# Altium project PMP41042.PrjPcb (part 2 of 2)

## Sheet PMP41042_sheet2.SchDoc
size A2; SheetNumber: 2; SheetTotal: 3
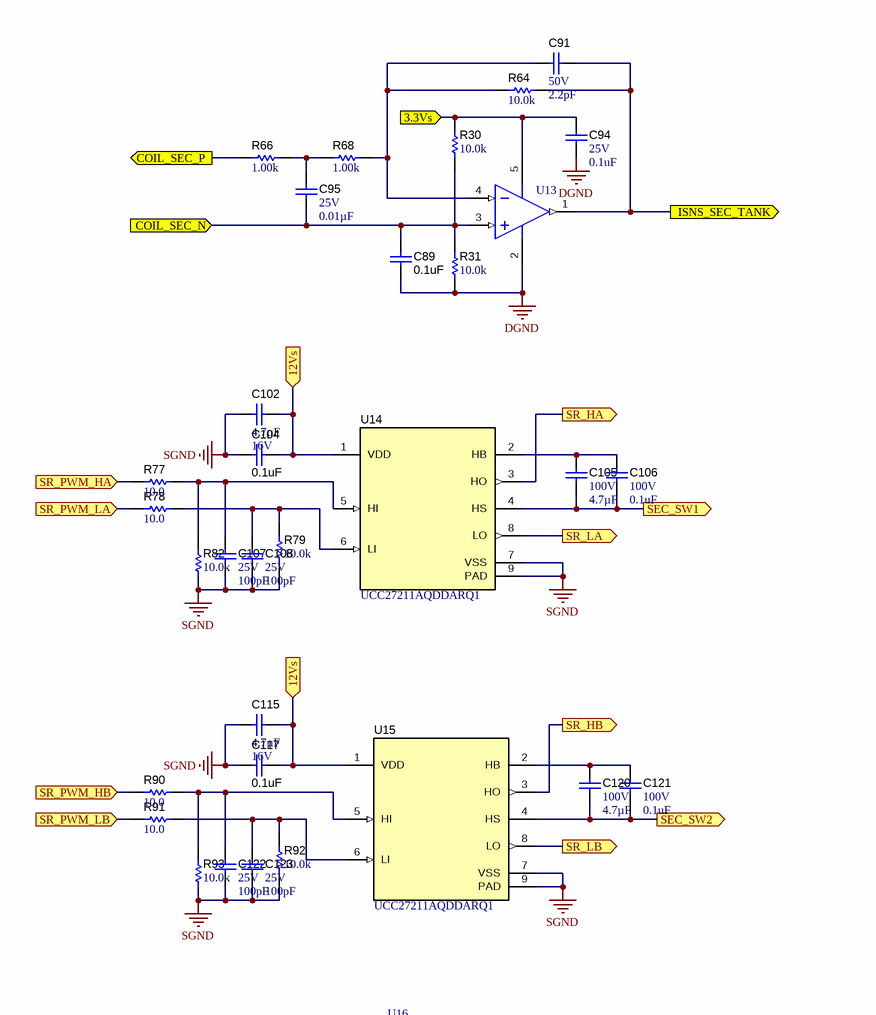
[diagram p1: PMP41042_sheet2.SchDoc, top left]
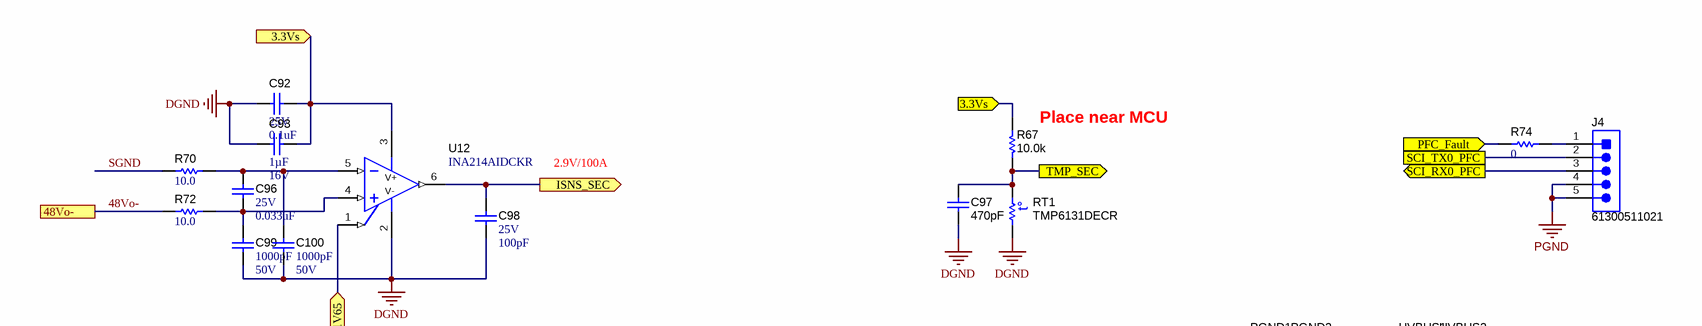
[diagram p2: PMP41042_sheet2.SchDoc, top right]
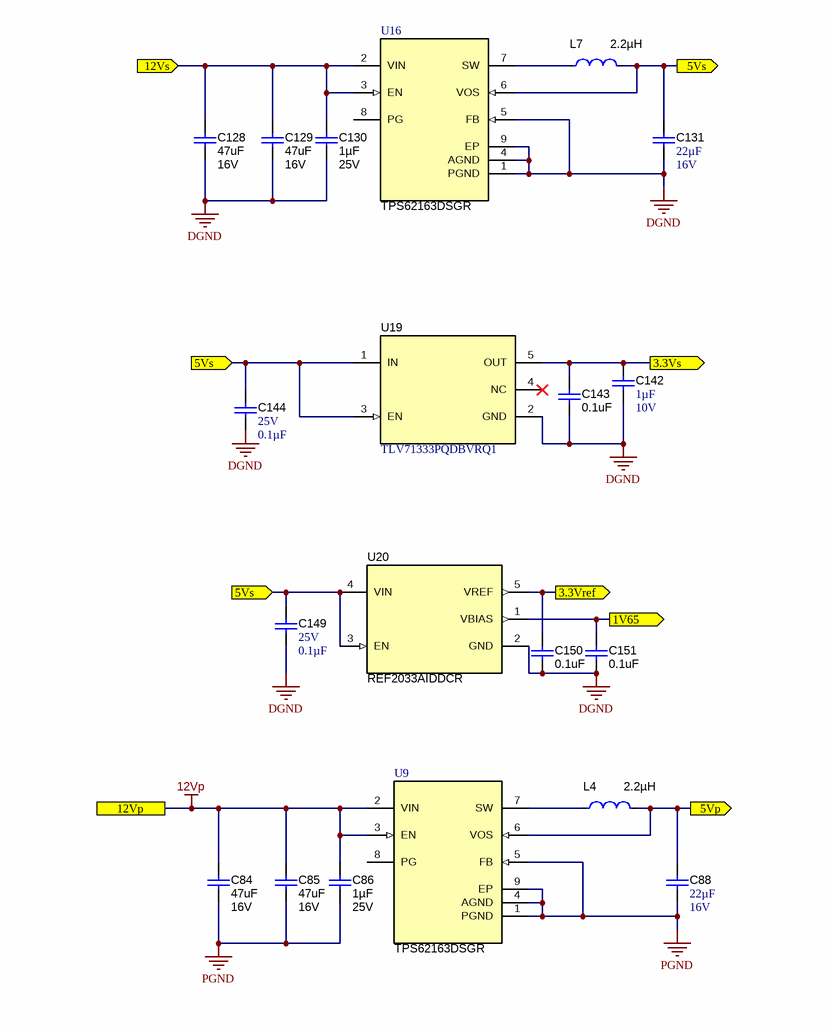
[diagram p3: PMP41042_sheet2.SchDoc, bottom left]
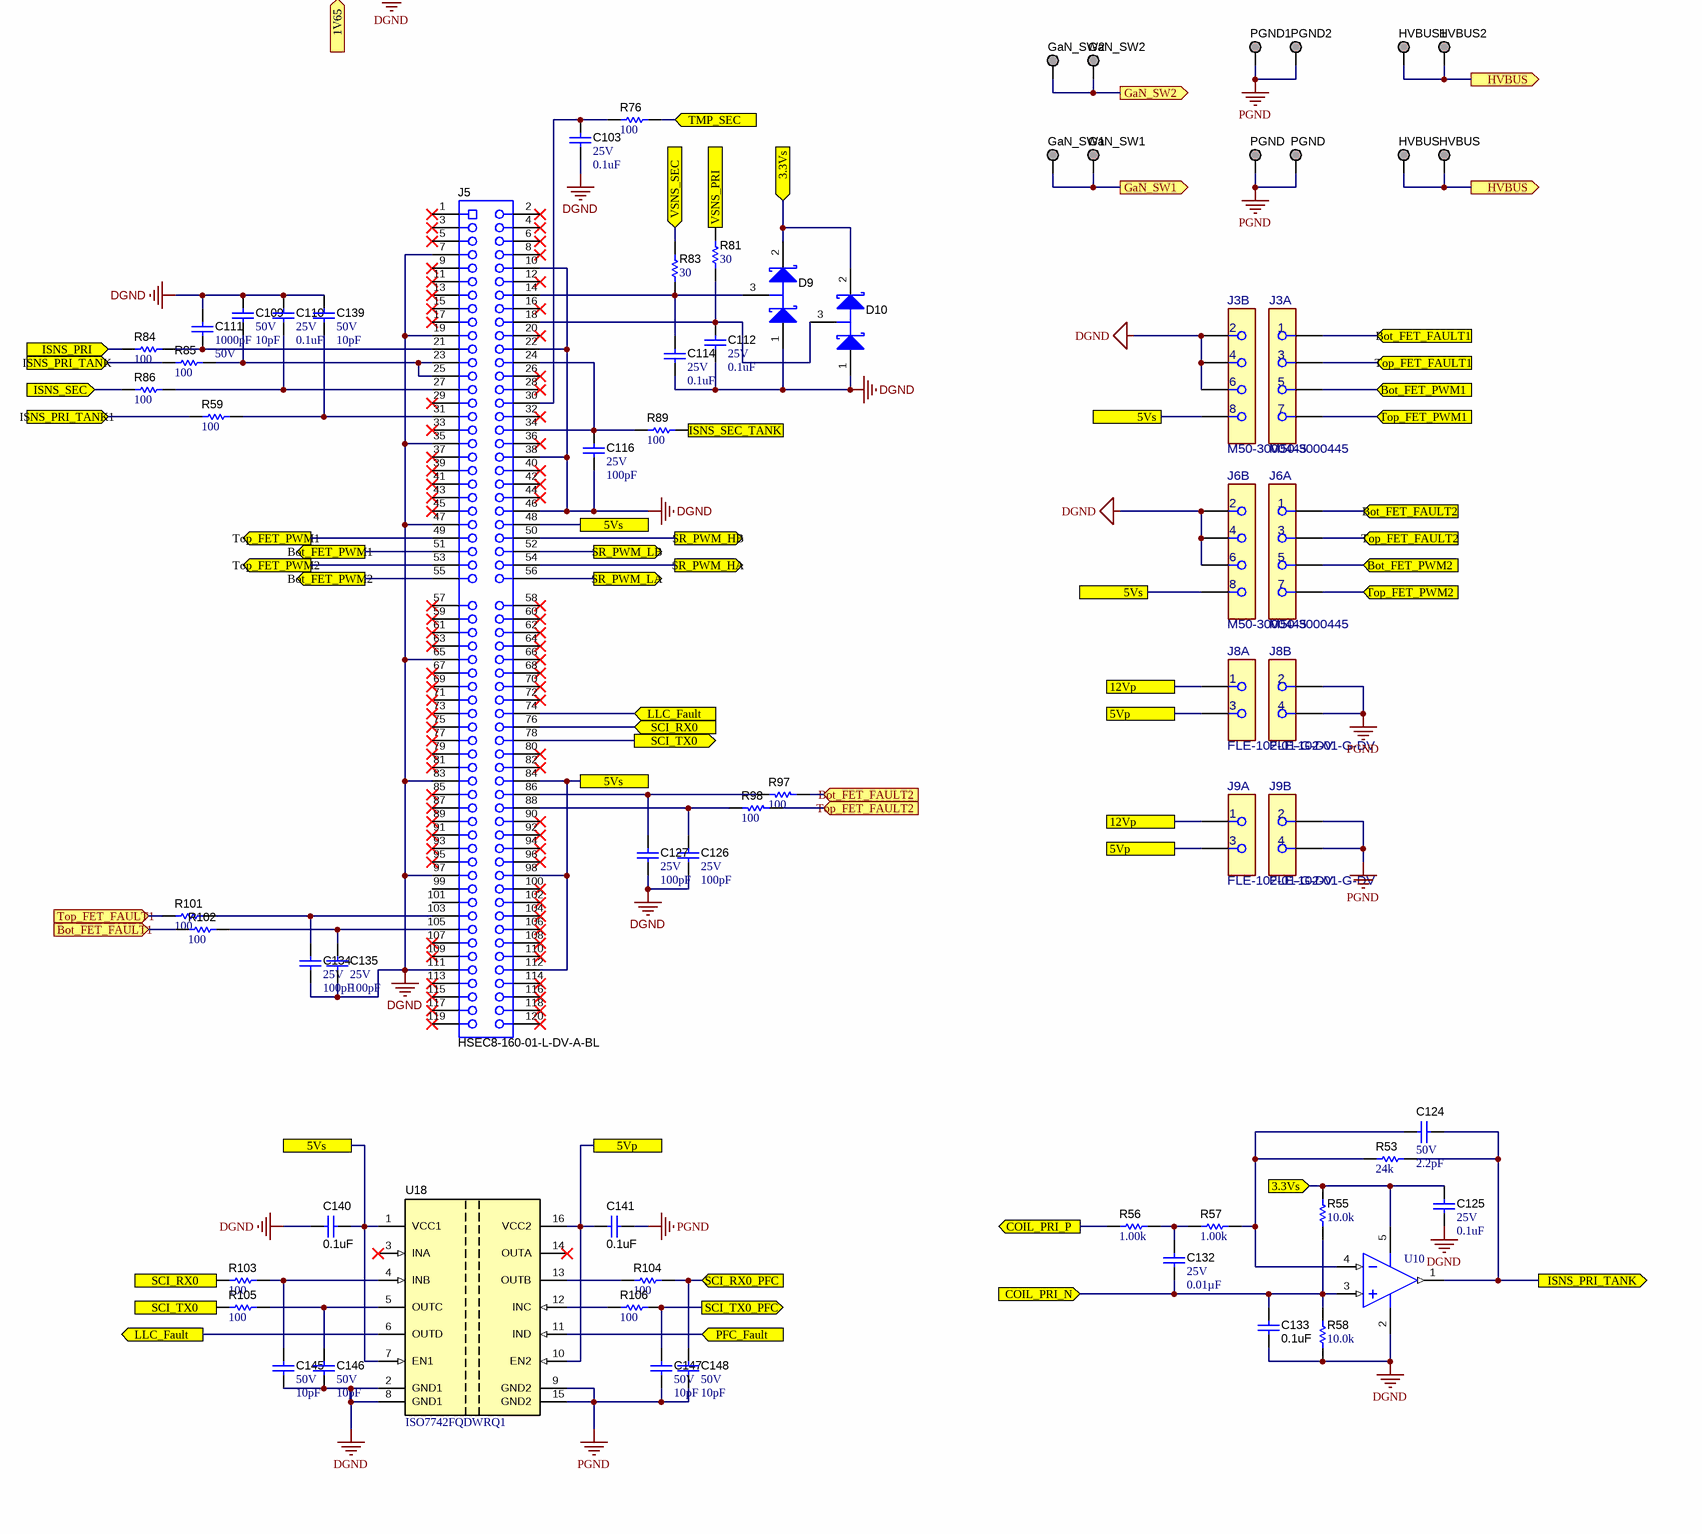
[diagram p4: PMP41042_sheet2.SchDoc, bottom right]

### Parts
(Parts that share a designator on the sheet are numbered #1, #2 ... from top to bottom, then left to right.)
C84  ValueDisplayed: 47uF  Value2: 16V  [1210_270]  (hidden comment: GRM32ER61C476KE15L)
C85  ValueDisplayed: 47uF  Value2: 16V  [1210_270]  (hidden comment: GRM32ER61C476KE15L)
C86  Cap_F: 1µF  VDC_V: 25V  [0805_HV]  (hidden comment: C0805C105K3RACTU)
C88  ValueDisplayed: 22µF  VDC_V: 16V  [0805_HV]  (hidden comment: CL21A226KOQNNNE)
C89  ValueDisplayed: 0.1uF  [0402]  (hidden comment: 0402YC104KAT2A)
C91  VDC_V: 50V  ValueDisplayed: 2.2pF  [0402]  (hidden comment: GRM1555C1H2R2CA01D)
C92  VDC_V: 25V  ValueDisplayed: 0.1uF  [0402]  (hidden comment: GRM155R71E104KE14D)
C93  Cap_F: 1µF  VDC_V: 16V  [0603]  (hidden comment: CGA3E1X7R1C105K080AC)
C94  VDC_V: 25V  ValueDisplayed: 0.1uF  [0402]  (hidden comment: GRM155R71E104KE14D)
C95  VDC_V: 25V  ValueDisplayed: 0.01µF  [0402]  (hidden comment: CL05B103KA5NNNC)
C96  VDC_V: 25V  ValueDisplayed: 0.033uF  [0402]  (hidden comment: GRM155R71E333KA88D)
C97  ValueDisplayed: 470pF  [0402]  (hidden comment: CGA2B2X7R1H471K050BA)
C98  VDC_V: 25V  ValueDisplayed: 100pF  [0402]  (hidden comment: C0402C101J3GACTU)
C99  ValueDisplayed: 1000pF  VDC_V: 50V  [0402]  (hidden comment: CL05B102KB5NNNC)
C100  ValueDisplayed: 1000pF  VDC_V: 50V  [0402]  (hidden comment: CL05B102KB5NNNC)
C102  Cap_F: 4.7µF  VDC_V: 16V  [0603]  (hidden comment: GRM188Z71C475KE21D)
C103  VDC_V: 25V  ValueDisplayed: 0.1uF  [0402]  (hidden comment: GRM155R71E104KE14D)
C104  ValueDisplayed: 0.1uF  [0402]  (hidden comment: 0402YC104KAT2A)
C105  VDC_V: 100V  ValueDisplayed: 4.7µF  [1206_190]  (hidden comment: 12061Z475MAT2A)
C106  VDC_V: 100V  ValueDisplayed: 0.1uF  [0402]  (hidden comment: GRM155R62A104KE14D)
C107  VDC_V: 25V  ValueDisplayed: 100pF  [0402]  (hidden comment: C0402C101J3GACTU)
C108  VDC_V: 25V  ValueDisplayed: 100pF  [0402]  (hidden comment: C0402C101J3GACTU)
C109  VDC_V: 50V  ValueDisplayed: 10pF  [0402]  (hidden comment: GRM1555C1H100JA01D)
C110  VDC_V: 25V  ValueDisplayed: 0.1uF  [0402]  (hidden comment: GRM155R71E104KE14D)
C111  ValueDisplayed: 1000pF  VDC_V: 50V  [0402]  (hidden comment: CL05B102KB5NNNC)
C112  VDC_V: 25V  ValueDisplayed: 0.1uF  [0402]  (hidden comment: GRM155R71E104KE14D)
C114  VDC_V: 25V  ValueDisplayed: 0.1uF  [0402]  (hidden comment: GRM155R71E104KE14D)
C115  Cap_F: 4.7µF  VDC_V: 16V  [0603]  (hidden comment: GRM188Z71C475KE21D)
C116  VDC_V: 25V  ValueDisplayed: 100pF  [0402]  (hidden comment: C0402C101J3GACTU)
C117  ValueDisplayed: 0.1uF  [0402]  (hidden comment: 0402YC104KAT2A)
C120  VDC_V: 100V  ValueDisplayed: 4.7µF  [1206_190]  (hidden comment: 12061Z475MAT2A)
C121  VDC_V: 100V  ValueDisplayed: 0.1uF  [0402]  (hidden comment: GRM155R62A104KE14D)
C122  VDC_V: 25V  ValueDisplayed: 100pF  [0402]  (hidden comment: C0402C101J3GACTU)
C123  VDC_V: 25V  ValueDisplayed: 100pF  [0402]  (hidden comment: C0402C101J3GACTU)
C124  VDC_V: 50V  ValueDisplayed: 2.2pF  [0402]  (hidden comment: GRM1555C1H2R2CA01D)
C125  VDC_V: 25V  ValueDisplayed: 0.1uF  [0402]  (hidden comment: GRM155R71E104KE14D)
C126  VDC_V: 25V  ValueDisplayed: 100pF  [0402]  (hidden comment: C0402C101J3GACTU)
C127  VDC_V: 25V  ValueDisplayed: 100pF  [0402]  (hidden comment: C0402C101J3GACTU)
C128  ValueDisplayed: 47uF  Value2: 16V  [1210_270]  (hidden comment: GRM32ER61C476KE15L)
C129  ValueDisplayed: 47uF  Value2: 16V  [1210_270]  (hidden comment: GRM32ER61C476KE15L)
C130  Cap_F: 1µF  VDC_V: 25V  [0805_HV]  (hidden comment: C0805C105K3RACTU)
C131  ValueDisplayed: 22µF  VDC_V: 16V  [0805_HV]  (hidden comment: CL21A226KOQNNNE)
C132  VDC_V: 25V  ValueDisplayed: 0.01µF  [0402]  (hidden comment: CL05B103KA5NNNC)
C133  ValueDisplayed: 0.1uF  [0402]  (hidden comment: 0402YC104KAT2A)
C134  VDC_V: 25V  ValueDisplayed: 100pF  [0402]  (hidden comment: C0402C101J3GACTU)
C135  VDC_V: 25V  ValueDisplayed: 100pF  [0402]  (hidden comment: C0402C101J3GACTU)
C139  VDC_V: 50V  ValueDisplayed: 10pF  [0402]  (hidden comment: GRM1555C1H100JA01D)
C140  ValueDisplayed: 0.1uF  [0402]  (hidden comment: C1005X7R1H104K050BB)
C141  ValueDisplayed: 0.1uF  [0402]  (hidden comment: C1005X7R1H104K050BB)
C142  Cap_F: 1µF  VDC_V: 10V  [0603]  (hidden comment: GRM188R71A105KA61D)
C143  ValueDisplayed: 0.1uF  [0402]  (hidden comment: CC0402KRX7R5BB104)
C144  VDC_V: 25V  ValueDisplayed: 0.1µF  [0402]  (hidden comment: CGA2B3X7R1E104K050BB)
C145  VDC_V: 50V  ValueDisplayed: 10pF  [0402]  (hidden comment: GRM1555C1H100JA01D)
C146  VDC_V: 50V  ValueDisplayed: 10pF  [0402]  (hidden comment: GRM1555C1H100JA01D)
C147  VDC_V: 50V  ValueDisplayed: 10pF  [0402]  (hidden comment: GRM1555C1H100JA01D)
C148  VDC_V: 50V  ValueDisplayed: 10pF  [0402]  (hidden comment: GRM1555C1H100JA01D)
C149  VDC_V: 25V  ValueDisplayed: 0.1µF  [0402]  (hidden comment: CGA2B3X7R1E104K050BB)
C150  ValueDisplayed: 0.1uF  [0402]  (hidden comment: CC0402KRX7R5BB104)
C151  ValueDisplayed: 0.1uF  [0402]  (hidden comment: CC0402KRX7R5BB104)
D9  BAT54S-7-F  [SOT-23]  (value not drawn)
D10  BAT54S-7-F  [SOT-23]  (value not drawn)
GaN_SW1#1  0312-0-15-15-34-27-10-0  [Mill-Max_0312-0-15-15-34-27-10-0]  (value not drawn)
GaN_SW1#2  0312-0-15-15-34-27-10-0  [Mill-Max_0312-0-15-15-34-27-10-0]  (value not drawn)
GaN_SW2#1  0312-0-15-15-34-27-10-0  [Mill-Max_0312-0-15-15-34-27-10-0]  (value not drawn)
GaN_SW2#2  0312-0-15-15-34-27-10-0  [Mill-Max_0312-0-15-15-34-27-10-0]  (value not drawn)
HVBUS1  0312-0-15-15-34-27-10-0  [Mill-Max_0312-0-15-15-34-27-10-0]  (value not drawn)
HVBUS2  0312-0-15-15-34-27-10-0  [Mill-Max_0312-0-15-15-34-27-10-0]  (value not drawn)
HVBUS#1  0312-0-15-15-34-27-10-0  [Mill-Max_0312-0-15-15-34-27-10-0]  (value not drawn)
HVBUS#2  0312-0-15-15-34-27-10-0  [Mill-Max_0312-0-15-15-34-27-10-0]  (value not drawn)
J3  M50-3000445  [FP-M50-3000445_CONN_SCKT_STRP8-MFG]  (parts A,B of 2)
J4  61300511021  [Wurth_61300511021]
J5  HSEC8-160-01-L-DV-A-BL  [controlCARD-120HSEC]
J6  M50-3000445  [FP-M50-3000445_CONN_SCKT_STRP8-MFG]  (parts A,B of 2)
J8  FLE-102-01-G-DV  [FP-FLE-102-01-G-DV_HDR4-MFG]  (parts A,B of 2)
J9  FLE-102-01-G-DV  [FP-FLE-102-01-G-DV_HDR4-MFG]  (parts A,B of 2)
L4  Ind_H: 2.2µH  [FP-74438336010_SMD2-MFG]  (hidden comment: 74438336022)
L7  Ind_H: 2.2µH  [FP-74438336010_SMD2-MFG]  (hidden comment: 74438336022)
PGND1  0312-0-15-15-34-27-10-0  [Mill-Max_0312-0-15-15-34-27-10-0]  (value not drawn)
PGND2  0312-0-15-15-34-27-10-0  [Mill-Max_0312-0-15-15-34-27-10-0]  (value not drawn)
PGND#1  0312-0-15-15-34-27-10-0  [Mill-Max_0312-0-15-15-34-27-10-0]  (value not drawn)
PGND#2  0312-0-15-15-34-27-10-0  [Mill-Max_0312-0-15-15-34-27-10-0]  (value not drawn)
R30  ValueDisplayed: 10.0k  [0402]  (hidden comment: CRCW040210K0FKED)
R31  ValueDisplayed: 10.0k  [0402]  (hidden comment: CRCW040210K0FKED)
R53  ValueDisplayed: 24k  [0402]  (hidden comment: CRCW040210K0FKED)
R55  ValueDisplayed: 10.0k  [0402]  (hidden comment: CRCW040210K0FKED)
R56  ValueDisplayed: 1.00k  [0402]  (hidden comment: CRCW04022K00FKED)
R57  ValueDisplayed: 1.00k  [0402]  (hidden comment: ERJ-2RKF1001X)
R58  ValueDisplayed: 10.0k  [0402]  (hidden comment: CRCW040210K0FKED)
R59  ValueDisplayed: 100  [0402]  (hidden comment: CRCW0402100RFKED)
R64  ValueDisplayed: 10.0k  [0402]  (hidden comment: CRCW04023K60JNED)
R66  ValueDisplayed: 1.00k  [0402]  (hidden comment: CRCW04022K00FKED)
R67  ValueDisplayed: 10.0k  [0402]  (hidden comment: Resistor)
R68  ValueDisplayed: 1.00k  [0402]  (hidden comment: ERJ-2RKF1001X)
R70  ValueDisplayed: 10.0  [0603]  (hidden comment: CRCW060310R0FKEA)
R72  ValueDisplayed: 10.0  [0603]  (hidden comment: CRCW060310R0FKEA)
R74  ValueDisplayed: 0  [0603]  (hidden comment: MCT06030Z0000ZP500)
R76  ValueDisplayed: 100  [0402]  (hidden comment: CRCW0402100RFKED)
R77  ValueDisplayed: 10.0  [0402]  (hidden comment: CRCW040210R0FKED)
R78  ValueDisplayed: 10.0  [0402]  (hidden comment: CRCW040210R0FKED)
R79  ValueDisplayed: 10.0k  [0402]  (hidden comment: CRCW040210K0FKED)
R81  ValueDisplayed: 30  [0402]  (hidden comment: CRCW040230R0JNED)
R82  ValueDisplayed: 10.0k  [0402]  (hidden comment: CRCW040210K0FKED)
R83  ValueDisplayed: 30  [0402]  (hidden comment: CRCW040230R0JNED)
R84  ValueDisplayed: 100  [0402]  (hidden comment: CRCW0402100RFKED)
R85  ValueDisplayed: 100  [0402]  (hidden comment: CRCW0402100RFKED)
R86  ValueDisplayed: 100  [0402]  (hidden comment: CRCW0402100RFKED)
R89  ValueDisplayed: 100  [0402]  (hidden comment: CRCW0402100RFKED)
R90  ValueDisplayed: 10.0  [0402]  (hidden comment: CRCW040210R0FKED)
R91  ValueDisplayed: 10.0  [0402]  (hidden comment: CRCW040210R0FKED)
R92  ValueDisplayed: 10.0k  [0402]  (hidden comment: CRCW040210K0FKED)
R93  ValueDisplayed: 10.0k  [0402]  (hidden comment: CRCW040210K0FKED)
R97  ValueDisplayed: 100  [0402]  (hidden comment: CRCW0402100RFKED)
R98  ValueDisplayed: 100  [0402]  (hidden comment: CRCW0402100RFKED)
R101  ValueDisplayed: 100  [0402]  (hidden comment: CRCW0402100RFKED)
R102  ValueDisplayed: 100  [0402]  (hidden comment: CRCW0402100RFKED)
R103  ValueDisplayed: 100  [0402]  (hidden comment: CRCW0402100RFKED)
R104  ValueDisplayed: 100  [0402]  (hidden comment: CRCW0402100RFKED)
R105  ValueDisplayed: 100  [0402]  (hidden comment: CRCW0402100RFKED)
R106  ValueDisplayed: 100  [0402]  (hidden comment: CRCW0402100RFKED)
RT1  TMP6131DECR  [DEC0002A]
U9  TPS62163DSGR  [DSG0008A]
U10  LMV116MF/NOPB  [DBV0005A_N]  (value not drawn)
U12  INA214AIDCKR  [DCK0006A_N]
U13  LMV116MF/NOPB  [DBV0005A_N]  (value not drawn)
U14  UCC27211AQDDARQ1  [DDA0008E_L]
U15  UCC27211AQDDARQ1  [DDA0008E_L]
U16  TPS62163DSGR  [DSG0008A]
U18  ISO7742FQDWRQ1  [DW0016B_HV]
U19  TLV71333PQDBVRQ1  [DBV0005A_N]
U20  REF2033AIDDCR  [DDC0005A_N]

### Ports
1V65 (in), 1V65 (out), 3.3Vref (out), 3.3Vs (in), 3.3Vs (out), 5Vp, 5Vp (out), 5Vs, 5Vs (in), 5Vs (out), 12Vp, 12Vs (in), 48Vo-, Bot_FET_FAULT1 (in), Bot_FET_FAULT2 (in), Bot_FET_PWM1 (in), Bot_FET_PWM1 (out), Bot_FET_PWM2 (in), Bot_FET_PWM2 (out), COIL_PRI_N (in), COIL_PRI_P (out), COIL_SEC_N (in), COIL_SEC_P (out), GaN_SW1 (out), GaN_SW2 (out), HVBUS (out), ISNS_PRI (in), ISNS_PRI_TANK1 (in), ISNS_PRI_TANK (in), ISNS_PRI_TANK (out), ISNS_SEC (in), ISNS_SEC (out), ISNS_SEC_TANK (in), ISNS_SEC_TANK (out), LLC_Fault (in), LLC_Fault (out), PFC_Fault (in), SCI_RX0 (in), SCI_RX0_PFC (in), SCI_RX0_PFC (out), SCI_TX0 (in), SCI_TX0 (out), SCI_TX0_PFC, SCI_TX0_PFC (out), SEC_SW1 (out), SEC_SW2 (out), SR_HA (out), SR_HB (out), SR_LA (out), SR_LB (out), SR_PWM_HA (in), SR_PWM_HA (out), SR_PWM_HB (in), SR_PWM_HB (out), SR_PWM_LA (in), SR_PWM_LA (out), SR_PWM_LB (in), SR_PWM_LB (out), TMP_SEC (in), TMP_SEC (out), Top_FET_FAULT1 (in), Top_FET_FAULT2 (in), Top_FET_PWM1 (in), Top_FET_PWM1 (out), Top_FET_PWM2 (in), Top_FET_PWM2 (out), VSNS_PRI (in), VSNS_SEC (in)

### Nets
12Vp: C84.2 C85.2 C86.1 J8.1 J9.1 U9.2(VIN) U9.3(EN) ; port 12Vp
DGND: C89.1 C92.1 C93.1 C94.1 C97.2 C98.2 C99.2 C100.2 C102.1 C103.1 C104.1 C107.2 C108.2 C109.1 C110.2 C111.1 C112.1 C114.1 C115.1 C116.2 C117.1 C122.2 C123.2 C125.1 C126.2 C127.2 C128.1 C129.1 C130.2 C131.2 C133.1 C134.2 C135.2 C139.1 C140.1 C142.2 C143.2 C144.2 C145.2 C146.2 C149.2 C150.2 C151.2 D9.1(A) D10.1(A) J3.2 J3.4 J3.6 J5.7 J5.10 J5.19 J5.22 J5.35 J5.38 J5.46 J5.47 J5.65 J5.83 J5.97 J5.111 J6.2 J6.4 J6.6 R31.1 R58.1 R70.1 R79.1 R82.1 R92.1 R93.1 RT1.1 U10.2(V-) U12.2(GND) U13.2(V-) U14.7(VSS) U14.9(PAD) U15.7(VSS) U15.9(PAD) U16.1(PGND) U16.4(AGND) U16.5(FB) U16.9(EP) U18.2(GND1) U18.8(GND1) U19.2(GND) U20.2(GND)  [also labelled SGND]
PGND: C84.1 C85.1 C86.2 C88.2 C141.2 C147.2 C148.2 J4.4 J4.5 J8.2 J8.4 J9.2 J9.4 PGND1.1 PGND2.1 PGND#1.1 PGND#2.1 U9.1(PGND) U9.4(AGND) U9.5(FB) U9.9(EP) U18.9(GND2) U18.15(GND2)
1V65: C151.1 U12.1(REF) U20.1(VBIAS) ; port 1V65
3.3Vref: C150.1 U20.5(VREF) ; port 3.3Vref
3.3Vs: C92.2 C93.2 C94.2 C125.2 C142.1 C143.1 D9.2(K) D10.2(K) R30.2 R55.2 R67.1 U10.5(V+) U12.3(V+) U13.5(V+) U19.5(OUT) ; port 3.3Vs
5Vp: C88.1 C141.1 J8.3 J9.3 L4.2 U9.6(VOS) U18.10(EN2) U18.16(VCC2) ; port 5Vp
5Vs: C131.1 C140.2 C144.1 C149.1 J3.8 J5.48 J5.84 J5.98 J5.112 J6.8 L7.2 U16.6(VOS) U18.1(VCC1) U18.7(EN1) U19.1(IN) U19.3(EN) U20.3(EN) U20.4(VIN) ; port 5Vs
12Vs: C102.2 C104.2 C115.2 C117.2 C128.2 C129.2 C130.1 U14.1(VDD) U15.1(VDD) U16.2(VIN) U16.3(EN) ; port 12Vs
48Vo-: R72.1 ; port 48Vo-
Bot_FET_FAULT1: J3.1 R102.1 ; port Bot_FET_FAULT1
Bot_FET_FAULT2: J6.1 R97.1 ; port Bot_FET_FAULT2
Bot_FET_PWM1: J3.5 J5.51 ; port Bot_FET_PWM1
Bot_FET_PWM2: J5.55 J6.5 ; port Bot_FET_PWM2
COIL_PRI_N: C132.2 C133.2 R55.1 R58.2 U10.3(IN+) ; port COIL_PRI_N
COIL_PRI_P: R56.1 ; port COIL_PRI_P
COIL_SEC_N: C89.2 C95.2 R30.1 R31.2 U13.3(IN+) ; port COIL_SEC_N
COIL_SEC_P: R66.1 ; port COIL_SEC_P
GaN_SW1: GaN_SW1#1.1 GaN_SW1#2.1 ; port GaN_SW1
GaN_SW2: GaN_SW2#1.1 GaN_SW2#2.1 ; port GaN_SW2
HVBUS: HVBUS1.1 HVBUS2.1 HVBUS#1.1 HVBUS#2.1 ; port HVBUS
ISNS_PRI: R84.1 ; port ISNS_PRI
ISNS_PRI_TANK: C124.1 R53.1 R85.2 U10.1(OUT) ; port ISNS_PRI_TANK
ISNS_PRI_TANK1: R59.1 ; port ISNS_PRI_TANK1
ISNS_SEC: C98.1 R86.1 U12.6(OUT) ; port ISNS_SEC
ISNS_SEC_TANK: C91.1 R64.2 R89.1 U13.1(OUT) ; port ISNS_SEC_TANK
LLC_Fault: J5.74 U18.6(OUTD) ; port LLC_Fault
PFC_Fault: R74.1 U18.11(IND) ; port PFC_Fault
SCI_RX0: J5.76 R103.1 ; port SCI_RX0
SCI_RX0_PFC: C148.1 J4.3 R104.2 ; port SCI_RX0_PFC
SCI_TX0: J5.78 R105.1 ; port SCI_TX0
SCI_TX0_PFC: C147.1 J4.2 R106.2 ; port SCI_TX0_PFC
SEC_SW1: C105.2 C106.2 U14.4(HS) ; port SEC_SW1
SEC_SW2: C120.2 C121.2 U15.4(HS) ; port SEC_SW2
SR_HA: U14.3(HO) ; port SR_HA
SR_HB: U15.3(HO) ; port SR_HB
SR_LA: U14.8(LO) ; port SR_LA
SR_LB: U15.8(LO) ; port SR_LB
SR_PWM_HA: J5.54 R77.1 ; port SR_PWM_HA
SR_PWM_HB: J5.50 R90.1 ; port SR_PWM_HB
SR_PWM_LA: J5.56 R78.1 ; port SR_PWM_LA
SR_PWM_LB: J5.52 R91.1 ; port SR_PWM_LB
TMP_SEC: C97.1 R67.2 R76.2 RT1.2 ; port TMP_SEC
Top_FET_FAULT1: J3.3 R101.1 ; port Top_FET_FAULT1
Top_FET_FAULT2: J6.3 R98.1 ; port Top_FET_FAULT2
Top_FET_PWM1: J3.7 J5.49 ; port Top_FET_PWM1
Top_FET_PWM2: J5.53 J6.7 ; port Top_FET_PWM2
VSNS_PRI: R81.2 ; port VSNS_PRI
VSNS_SEC: R83.2 ; port VSNS_SEC
NetC91_2: C91.2 R64.1 R68.2 U13.4(IN-)
NetC95_1: C95.1 R66.2 R68.1
NetC96_1: C96.1 C100.1 R70.2 U12.5(IN-)
NetC96_2: C96.2 C99.1 R72.2 U12.4(IN+)
NetC103_2: C103.2 J5.30 R76.1
NetC105_1: C105.1 C106.1 U14.2(HB)
NetC107_1: C107.1 R77.2 R82.2 U14.5(HI)
NetC108_1: C108.1 R78.2 R79.2 U14.6(LI)
NetC109_2: C109.2 J5.23 J5.25 R85.1
NetC110_1: C110.1 J5.27 R86.2
NetC111_2: C111.2 J5.21 R84.2
NetC112_2: C112.2 D10.3(C) J5.18 R81.1
NetC114_2: C114.2 D9.3(C) J5.14 R83.1
NetC116_1: C116.1 J5.24 J5.34 R89.2
NetC120_1: C120.1 C121.1 U15.2(HB)
NetC122_1: C122.1 R90.2 R93.2 U15.5(HI)
NetC123_1: C123.1 R91.2 R92.2 U15.6(LI)
NetC124_2: C124.2 R53.2 R57.2 U10.4(IN-)
NetC126_1: C126.1 J5.88 R98.2
NetC127_1: C127.1 J5.86 R97.2
NetC132_1: C132.1 R56.2 R57.1
NetC134_1: C134.1 J5.103 R101.2
NetC135_1: C135.1 J5.105 R102.2
NetC139_2: C139.2 J5.31 R59.2
NetC145_1: C145.1 R103.2 U18.4(INB)
NetC146_1: C146.1 R105.2 U18.5(OUTC)
NetJ4_1: J4.1 R74.2
NetL4_1: L4.1 U9.7(SW)
NetL7_1: L7.1 U16.7(SW)
NetR104_1: R104.1 U18.13(OUTB)
NetR106_1: R106.1 U18.12(INC)

Not connected (* = marked no-connect by the designer): J5 1* 2* 3* 4* 5* 6* 8* 9* 11* 12* 13* 15* 16* 17* 20* 26* 28* 29* 32* 33* 36* 37* 39* 40* 41* 42* 43* 44* 45* 57* 58* 59* 60* 61* 62* 63* 64* 66* 67* 68* 69* 70* 71* 72* 73* 75* 77* 79* 80* 81* 82* 85* 87* 89* 90* 91* 92* 93* 94* 95* 96* 99 100* 101 102* 104* 106* 107* 108* 109* 110* 113* 114* 115* 116* 117* 118* 119* 120*; U9 8(PG); U16 8(PG); U18 3(INA)* 14(OUTA)*; U19 4(NC)*

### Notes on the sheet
- (near R67) Place near MCU
- 2.9V/100A

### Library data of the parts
C84 C85 C128 C129 = CMP-0009211-2: CAP, CERM, 47 uF, 16 V, +/- 10%, X5R, 1210; Manufacturer: MuRata; Polarized: N; Value: 47uF; U/M: EA; Cap_F: 47µF; Value1: Unknown; TaMin_C: -55°C; TaMax_C: 85°C; Cap_Case: 1210; SizeArea_mm2: 8; SizeAreaWB_mm2: 14.7; SizeX_mm: 3.2; SizeY_mm: 2.5; SizeZ_mm: 2.7; AEC Category: Q200
C86 C130 = CMP-0007728-2: CAP, CERM, 1 uF, 25 V, +/- 10%, X7R, 0805; Manufacturer: Kemet; TaMin_C: -55°C; Polarized: N; SizeAreaWB_mm2: 6.75; Value1: Unknown; U/M: EA; Value: 1uF; TaMax_C: 125°C; SizeZ_mm: 1.45; SizeX_mm: 2; SizeY_mm: 1.25; Cap_Case: 0805; SizeArea_mm2: 2.5; AEC Category: Q200
C88 C131 = CMP-0085852-1: CAP, CERM, 22 µF, 16 V,+/- 10%, X5R, 0805; Manufacturer: Samsung Electro-Mechanics; SizeX_mm: 2; TaMax_C: 85°C; AEC Category: Q200; SizeY_mm: 1.25; TaMin_C: -55°C; SizeZ_mm: 1.45; U/M: EA; Polarized: N; SizeArea_mm2: 2.5; Cap_Case: 0805; SizeAreaWB_mm2: 6.75; Value: 22uF
C89 C104 C117 C133 = CMP-0006201-2: CAP, CERM, 0.1 uF, 16 V, +/- 10%, X7R, 0402; Manufacturer: AVX; Polarized: N; Value: 0.1uF; U/M: EA; Cap_F: 100nF; Value1: Unknown; VDC_V: 16V; TaMin_C: -55°C; TaMax_C: 125°C; SizeArea_mm2: 0.5; SizeAreaWB_mm2: 3; SizeX_mm: 1; SizeZ_mm: 0.6; AEC Category: Q200
C91 C124 = CMP-0006448-1: CAP, CERM, 2.2 pF, 50 V, +/- 5%, C0G/NP0, 0402; Manufacturer: MuRata; TaMin_C: -55°C; Polarized: N; SizeAreaWB_mm2: 3; Value1: Unknown; U/M: EA; Value: 2.2pF; TaMax_C: 125°C; SizeZ_mm: 0.6; SizeX_mm: 1; SizeY_mm: 0.5; AEC Category: Q200
C92 C94 C103 C110 C112 C114 C125 = CMP-0006659-2: CAP, CERM, 0.1 uF, 25 V, +/- 10%, X7R, 0402; Manufacturer: MuRata; TaMin_C: -55°C; Polarized: N; SizeAreaWB_mm2: 3; Value1: Unknown; U/M: EA; Value: 0.1uF; TaMax_C: 125°C; SizeZ_mm: 0.6; SizeX_mm: 1; SizeY_mm: 0.5; Cap_F: 100nF; AEC Category: Q200
C93 = CMP-0079607-1: CAP, CERM, 1 µF, 16 V,+/- 10%, X7R, AEC-Q200 Grade 1, 0603; Manufacturer: TDK; TaMin_C: -55°C; Polarized: N; SizeAreaWB_mm2: 4.68; U/M: EA; Value: 1uF; TaMax_C: 125°C; SizeZ_mm: 1; SizeX_mm: 1.6; SizeY_mm: 0.8; SizeArea_mm2: 1.28; AEC Qualified: Y; AEC Category: Q200
C95 C132 = CMP-0860561-1: CAP, CERM, 0.01 µF, 25 V,+/- 10%, X7R, 0402; Manufacturer: Samsung Electro-Mechanics; U/M: EA; SizeArea_mm2: 0.5; Value: 0.01uF; TaMin_C: -55°C; SizeZ_mm: 0.6; Polarized: N; SizeX_mm: 1; TaMax_C: 125°C; SizeAreaWB_mm2: 3; Cap_F: 10nF; AEC Category: Q200
C96 = CMP-0006666-2: CAP, CERM, 0.033 uF, 25 V, +/- 10%, X7R, 0402; Manufacturer: MuRata; TaMin_C: -55°C; Polarized: N; SizeAreaWB_mm2: 3; Value1: Unknown; U/M: EA; TaMax_C: 125°C; SizeZ_mm: 0.6; SizeX_mm: 1; SizeY_mm: 0.5; Cap_F: 33nF; AEC Category: Q200
C97 = CMP-0006320-2: CAP, CERM, 470 pF, 50 V, +/- 10%, X7R, AEC-Q200 Grade 1, 0402; Manufacturer: TDK; TaMin_C: -55°C; ESR_ohm: 4.96489; Polarized: N; SizeAreaWB_mm2: 3; Value1: 4.96489 ohm; U/M: EA; Value: 470pF; TaMax_C: 125°C; SizeZ_mm: 0.6; SizeX_mm: 1; SizeY_mm: 0.5; Value2: 50V; CompType: Capacitor; AEC Qualified: Y; IRMS_A: 2.28414dA; AEC Category: Q200
C98 C107 C108 C116 C122 C123 C126 C127 C134 C135 = CMP-0006233-1: CAP, CERM, 100 pF, 25 V, +/- 5%, C0G/NP0, 0402; Manufacturer: Kemet; TaMin_C: -55°C; Polarized: N; SizeAreaWB_mm2: 3; Value1: Unknown; U/M: EA; Value: 100pF; TaMax_C: 125°C; SizeZ_mm: 0.6; SizeX_mm: 1; SizeY_mm: 0.5; AEC Category: Q200
C99 C100 C111 = CMP-0860560-1: CAP, CERM, 1000 pF, 50 V,+/- 10%, X7R, 0402; Manufacturer: Samsung Electro-Mechanics; SizeArea_mm2: 0.5; TaMin_C: -55°C; AEC Qualified: N; TaMax_C: 125°C; SizeZ_mm: 0.6; Green_Lifecycle: Active; Green_REACh: Incomplete; SizeX_mm: 1; Cap_F: 1nF; AEC Category: Q200; SizeAreaWB_mm2: 3; Value: 1000pF; U/M: EA
C102 C115 = CMP-0064936-4: CAP, CERM, 4.7 uF, 16 V,+/- 10%, X7R, 0603; Manufacturer: MuRata; TaMin_C: -55°C; Polarized: N; SizeAreaWB_mm2: 4.68; Value1: Unknown; U/M: EA; Value: 4.7uF; TaMax_C: 125°C; SizeZ_mm: 1; SizeX_mm: 1.6; SizeY_mm: 0.8; SizeArea_mm2: 1.28; AEC Category: Q200
C105 C120 = CMP-0078499-1: CAP, CERM, 4.7 µF, 100 V,+/- 20%, X7S, 1206; Manufacturer: AVX; TaMin_C: -55°C; Polarized: N; SizeAreaWB_mm2: 10.92; U/M: EA; Value: 4.7uF; TaMax_C: 125°C; SizeZ_mm: 1.9; SizeX_mm: 3.2; SizeY_mm: 1.6; Cap_Case: 1206; SizeArea_mm2: 5.12; AEC Category: Q200
C106 C121 = CMP-0006618-1: CAP, CERM, 0.1 uF, 100 V, +/- 10%, X5R, 0402; Manufacturer: MuRata; TaMin_C: -55°C; Polarized: N; SizeAreaWB_mm2: 3; Value1: Unknown; U/M: EA; Value: 0.1uF; TaMax_C: 85°C; SizeZ_mm: 0.6; SizeX_mm: 1; SizeY_mm: 0.5; Cap_F: 100nF; AEC Category: Q200
C109 C139 C145-C148 = CMP-0006408-1: CAP, CERM, 10 pF, 50 V, +/- 5%, C0G/NP0, 0402; Manufacturer: MuRata; TaMin_C: -55°C; Polarized: N; SizeAreaWB_mm2: 3; Value1: Unknown; U/M: EA; Value: 10pF; TaMax_C: 125°C; SizeZ_mm: 0.6; SizeX_mm: 1; SizeY_mm: 0.5; AEC Category: Q200
C140 C141 = CMP-0006297-2: CAP, CERM, 0.1 uF, 50 V, +/- 10%, X7R, 0402; Manufacturer: TDK; Alternate PartNumber: 885012205037; Alternate Manufacturer: Wurth Elektronik; Polarized: N; Value: 0.1uF; U/M: EA; Cap_F: 100nF; ESR_ohm: 0.039064; Value1: 0.039064 ohm; VDC_V: 50V; IRMS_A: 8.14669dA; TaMin_C: -55°C; TaMax_C: 125°C; SizeArea_mm2: 0.5; SizeAreaWB_mm2: 3; SizeX_mm: 1; SizeZ_mm: 0.6; AEC Category: Q200
C142 = CMP-0007365-1: CAP, CERM, 1 uF, 10 V, +/- 10%, X7R, 0603; Manufacturer: MuRata; TaMin_C: -55°C; ESR_ohm: 11m; Polarized: N; SizeAreaWB_mm2: 4.68; Value1: 0.011 ohm; U/M: EA; Value: 1uF; TaMax_C: 125°C; SizeZ_mm: 1; SizeX_mm: 1.6; SizeY_mm: 0.8; SizeArea_mm2: 1.28; AEC Category: Q200
C143 C150 C151 = GRM155R70J104KA01D: CAP, CERM, 0.1uF, 6.3V, +/-10%, X7R, 0402; Manufacturer: Yageo; Polarized: N; CompType: Capacitor; U/M: EA; Cap_F: 0.0000001; Tolerance_%: 10; Value1: Unknown; VDC_V: 6.3; TaMin_C: -55; TaMax_C: 125
C144 C149 = CMP-0080610-1: CAP, CERM, 0.1 µF, 25 V,+/- 10%, X7R, AEC-Q200 Grade 1, 0402; Manufacturer: TDK; TaMin_C: -55°C; Polarized: N; SizeAreaWB_mm2: 3; U/M: EA; Value: 0.1uF; TaMax_C: 125°C; SizeZ_mm: 0.6; SizeX_mm: 1; SizeY_mm: 0.5; AEC Qualified: Y; Cap_F: 100nF; AEC Category: Q200
D9 D10 = CMP-0028456-1: Diode, Schottky, 30 V, 0.2 A, SOT-23; Manufacturer: Diodes Inc.; Io_A: 2dA; Green_Lifecycle: Active; SizeAreaWB_mm2: 14; Vr_V: 30V; Green_REACh: Passed; Value1: 0.2A; TJmax_C: 125°C; U/M: EA; Value: 30V; SizeZ_mm: 1.1; SizeX_mm: 2.5; SizeY_mm: 3; Vf_V: 6.5dV; Value2: 0.65V; SizeArea_mm2: 7.5; AEC Category: Q101
GaN_SW1#1 GaN_SW1#2 GaN_SW2#1 GaN_SW2#2 HVBUS1 HVBUS2 HVBUS#1 HVBUS#2 PGND1 PGND2 PGND#1 PGND#2 = CMP-0055026-1: Manufacturer: Mill-Max; CNHeader: FALSE; Green_Lifecycle: Active; Gender: Female; Green_REACh: Passed; CompType: Pin Receptacle; ContactFinish: Gold
J3 J6 = CMP-0097755-1: Conn Socket Strip SKT 8 POS 1.27mm Solder ST Thru-Hole; Manufacturer: Harwin; Conn Orientation: Vertical; Conn Gender: Female; Current_A: 1A; AEC Qualified: No; Is Female: yes; ContactFinish: Gold,Nickel; SizeZ_mm: 4.55mm; Row_Count: 2
J4 = CMP-0054800-1: Header, 2.54 mm, 5x1, Gold, R/A, TH; Manufacturer: Wurth Elektronik; CNHeader: TRUE; Shrouded: N; Gender: Male; Row_Count: 1; Pitch_mm: 2.54; CT: FALSE
J5 = CMP-0003814-2: C2000 controlCARD-120HSEC connector, SMT; Manufacturer: Samtec; Note: The pin numbering does not match Samtec datasheet
J8 J9 = CMP-0097647-1: Manufacturer: Samtec; Category Bda670Ac885E6661: Uncategorized; SizeZ_mm: 4.68mm; DUT-Pitch_mm: 1.27mm; Current_A: 2.9A; ContactFinish: Gold,Nickel; Category E7012A0Bd22E3Cc6: Headers & Receptacles; Conn Orientation: Vertical; Row_Count: 2; Category 0836C53C3D42D3F1: Connectors; Is Female: yes; AEC Qualified: No; Category A0826D8895867B45: Rectangular Industrial Connectors; Conn Gender: Female; Category 75Fab8F04590Ae3D: Connectors and Adapters
L4 L7 = CMP-0087867-1: 2.2µH Shielded Molded Inductor 2.4A 67mOhm Max 2-SMD; Manufacturer: Wurth Electronics; SizeZ_mm: 2mm; Material: Metal Composite; Isat: 4.3A; Symbol Name: SYM-74438336010; DCR_ohm: 0.032; AEC Grade: Grade 1; AEC Qualified: Yes
R30 R31 R55 R58 = CMP-0025958-1: RES, 10.0 k, 1%, 0.063 W, 0402; Manufacturer: Vishay-Dale; Power_W: 63mW; TempCo: 100 ppm/C; Value_Code: 10k0; U/M: EA; Value: 10.0k; EIA_Code: E96; Res_ohm: 10k; SizeX_mm: 1; SizeY_mm: 0.5; SizeZ_mm: 0.6; Value2: 0.063W; VDC_V: 50V; AEC Category: Q200
R53 = CMP-0026883-3: RES, 24 k, 5%, 0.063 W, AEC-Q200 Grade 0, 0402; Manufacturer: Vishay-Dale; PartNumber: CRCW040224K0JNED; Power_W: 63mW; TempCo: 200 ppm/C; Value_Code: 24k0; Value: 24k; EIA_Code: E24; SizeX_mm: 1; SizeY_mm: 0.5; SizeZ_mm: 0.6; Value2: 0.063W; AEC Qualified: Y; VDC_V: 50V; AEC Category: Q200; AEC Grade: 0
R56 R66 = CMP-0026657-1: RES, 1.00 k, 1%, 0.1 W, 0402; Manufacturer: Panasonic; PartNumber: ERJ-2RKF1001X; Power_W: 100mW; TempCo: 100 ppm/C; Value_Code: 1k00; U/M: EA; Value: 1.00k; EIA_Code: E96; Res_ohm: 1k; SizeX_mm: 1; SizeY_mm: 0.5; SizeZ_mm: 0.6; Value2: 0.1W; VDC_V: 50V; AEC Category: Q200
R57 R68 = CMP-0026657-1: RES, 1.00 k, 1%, 0.1 W, 0402; Manufacturer: Panasonic; Power_W: 100mW; TempCo: 100 ppm/C; Value_Code: 1k00; U/M: EA; Value: 1.00k; EIA_Code: E96; Res_ohm: 1k; SizeX_mm: 1; SizeY_mm: 0.5; SizeZ_mm: 0.6; Value2: 0.1W; VDC_V: 50V; AEC Category: Q200
R59 R76 R84-R86 R89 R97 R98 R101-R106 = CMP-0025951-1: RES, 100, 1%, 0.063 W, 0402; Manufacturer: Vishay-Dale; Power_W: 63mW; TempCo: 100 ppm/C; Value_Code: 100R; U/M: EA; Value: 100; EIA_Code: E96; SizeX_mm: 1; SizeY_mm: 0.5; SizeZ_mm: 0.6; Value2: 0.063W; VDC_V: 50V; AEC Category: Q200
R64 = CMP-0025958-1: RES, 10.0 k, 1%, 0.063 W, 0402; Manufacturer: Vishay-Dale; PartNumber: CRCW040210K0FKED; Power_W: 63mW; TempCo: 100 ppm/C; Value_Code: 10k0; U/M: EA; Value: 10.0k; EIA_Code: E96; Res_ohm: 10k; SizeX_mm: 1; SizeY_mm: 0.5; SizeZ_mm: 0.6; Value2: 0.063W; VDC_V: 50V; AEC Category: Q200
R67 = CMP-0025958-3: RES, 10.0 k, 1%, 0.063 W, AEC-Q200 Grade 0, 0402; PartNumber: CRCW040210K0FKED; Manufacturer: Vishay-Dale; Value: 10.0k; Res_ohm: 10k; Value_Code: 10k0; Power_W: 63mW; Value2: 0.063W; VDC_V: 50V; TempCo: 100 ppm/C; SizeArea_mm2: 0.5; SizeX_mm: 1; SizeZ_mm: 0.6; EIA_Code: E96; AEC Category: Q200; AEC Qualified: Y; AEC Grade: 0
R70 R72 = CMP-0022003-4: RES, 10.0, 1%, 0.1 W, AEC-Q200 Grade 0, 0603; Manufacturer: Vishay-Dale; Power_W: 100mW; TempCo: 100 ppm/C; Value_Code: 10R0; Value: 10.0; EIA_Code: E96; Res_ohm: 10; SizeX_mm: 1.6; SizeY_mm: 0.8; SizeZ_mm: 1; Value2: 0.1W; SizeArea_mm2: 1.28; AEC Qualified: Y; VDC_V: 75V; AEC Category: Q200; AEC Grade: 0
R74 = CMP-0025884-2: RES, 0, 5%, 0.125 W, 0603; Manufacturer: Vishay/Beyschlag; Power_W: 125mW; TempCo: ppm/C; Value_Code: 0000; U/M: EA; Value: 0; EIA_Code: E24; SizeX_mm: 1.6; SizeY_mm: 0.8; SizeZ_mm: 1; Value2: 0.125W; SizeArea_mm2: 1.28; AEC Qualified: N; AEC Category: Q200
R77 R78 R90 R91 = CMP-0025963-3: RES, 10.0, 1%, 0.063 W, AEC-Q200 Grade 0, 0402; Manufacturer: Vishay-Dale; Power_W: 63mW; TempCo: 100 ppm/C; Value_Code: 10R0; Value: 10.0; EIA_Code: E96; Res_ohm: 10; SizeX_mm: 1; SizeY_mm: 0.5; SizeZ_mm: 0.6; Value2: 0.063W; AEC Qualified: Y; VDC_V: 50V; AEC Category: Q200; AEC Grade: 0
R79 R82 R92 R93 = CMP-0025958-2: RES, 10.0 k, 1%, 0.063 W, 0402; Manufacturer: Vishay-Dale; Power_W: 63mW; TempCo: 100 ppm/C; Value_Code: 10k0; U/M: EA; Value: 10.0k; EIA_Code: E96; Res_ohm: 10k; SizeX_mm: 1; SizeY_mm: 0.5; SizeZ_mm: 0.6; Value2: 0.063W; VDC_V: 50V; AEC Category: Q200
R81 R83 = CMP-0026904-3: RES, 30, 5%, 0.063 W, AEC-Q200 Grade 0, 0402; Manufacturer: Vishay-Dale; Power_W: 63mW; TempCo: 200 ppm/C; Value_Code: 30R0; Value: 30; EIA_Code: E24; SizeX_mm: 1; SizeY_mm: 0.5; SizeZ_mm: 0.6; Value2: 0.063W; AEC Qualified: Y; VDC_V: 50V; AEC Category: Q200; AEC Grade: 0
RT1 = CMP-0084566-1: Thermistor, DEC0002A (X1SON-2); Alternate Manufacturer: Texas Instruments; Alternate PartNumber: TMP6131DECT; CompType: IC; AEC Category: Q200; SizeX_mm: 1; AEC Qualified: N; SizeZ_mm: 0.5; SizeArea_mm2: 0.6; SizeAreaWB_mm2: 3.2
U9 U16 = CMP-0037791-2: Buck Step Down Regulator with 3 to 17 V Input and 5 V Output, -40 to 85 degC, 8-Pin WSON (DSG), Green (RoHS & no Sb/Br); Manufacturer: Texas Instruments; Vin(Min)(V): 3; Switch Current Limit(Typ)(A): 1.8; Vin(Max)(V): 17; Rating: Catalog; Vout(Min)(V): 5; Regulated Outputs(#): 1; Duty Cycle(Max)(%): 100; SubFamily: Step-Down Regulator; Synchronous Rectification: TRUE; Iq(Typ)(mA): 0.017
U10 U13 = CMP-0068461-1: Low Voltage, 45MHz, Rail-to-Rail Output Operational Amplifiers with Shutdown Option, 5-pin SOT-23, Pb-Free; Manufacturer: Texas Instruments; PowerWise: N; PackageTopMarking: AC1A*XTT
U12 = CMP-0077332-3: 26-V, Bi-Directional, Zero-Drift, High Accuracy, Low-/High-Side, Voltage Out Current Shunt Monitor, DCK0006A (SOT-SC70-6); Manufacturer: Texas Instruments; Alternate PartNumber: INA214AIDCKT; SizeX_mm: 2.1; SizeArea_mm2: 4.2; CompType: IC; Rating: Catalog; SizeY_mm: 2.0; SizeZ_mm: 1.1; SizeAreaWB_mm2: 9.3; AEC Qualified: N; AEC Category: Q200
U14 U15 = CMP-0073887-2: 120-V Boot, 4-A Peak, High-Frequency High-Side and Low-Side Driver, DDA0008E (SOIC-8); Manufacturer: Texas Instruments; SizeZ_mm: 1.7; SizeX_mm: 5.0; SizeY_mm: 6.2; SizeArea_mm2: 31.0; CompType: IC; U/M: EA; SizeAreaWB_mm2: 57.4
U18 = CMP-0076066-3: Automotive, High Speed, Robust EMC Quad-Channel Digital Isolators, DW0016B (SOIC-16); Alternate Manufacturer: Texas Instruments; Alternate PartNumber: ISO7742FQDWQ1; SizeX_mm: 10.4; SizeArea_mm2: 107.12; SizeZ_mm: 2.65; SizeY_mm: 10.3; AEC Category: Q200; AEC Qualified: Y; CompType: IC; SizeAreaWB_mm2: 152.52
U19 = CMP-0073750-1: Capacitor-Free, 150-mA, LDO Regulator w/ Foldback Current Limit, DBV0005A (SOT-23-5); Alternate Manufacturer: Texas Instruments; SizeAreaWB_mm2: 14.82; U/M: EA; SizeZ_mm: 1.45; SizeX_mm: 2.8; SizeY_mm: 2.9; SizeArea_mm2: 8.12; CompType: IC
U20 = CMP-0066190-1: Low-Drift, Low-Power, Dual-Output VREF and VREF/2 Voltage Reference, DDC0005A (SOT-23-T-5); Alternate PartNumber: REF2033AIDDCT; Alternate Manufacturer: Texas Instruments; SizeAreaWB_mm2: 14.82; U/M: EA; SizeZ_mm: 1.1; SizeX_mm: 2.8; SizeY_mm: 2.9; SizeArea_mm2: 8.12; CompType: IC

## Sheet BIAS.SchDoc
size A3; Date: Not shown in title block; ApprovedBy: Not shown in title block; CheckedBy: Not shown in title block; Author: Not shown in title block; CompanyName: Not shown in title block; Engineer: Not shown in title block; Organization: Not shown in title block; Address1: Not shown in title block; Address2: Not shown in title block; Address3: Not shown in title block; Address4: Not shown in title block; DocumentNumber: 1; Revision: Use project parameter SCH_Rev; SheetNumber: 3; SheetTotal: 3; PageSetup: Record=PageOptions¦CenterHorizontal=True¦CenterVertical=True¦PrintScale=0.93¦XCorrection=1.00¦YCorrection=1.00¦PrintKind=0¦BorderSize=5000000¦LeftOffset=0¦BottomOffset=0¦Orientation=2¦PaperLength=1000¦PaperWidth=1000¦Scale=100¦PaperSource=15¦PrintQuality=600¦MediaType=1¦DitherType=10¦PaperKind=Letter¦PrintScaleMode=1
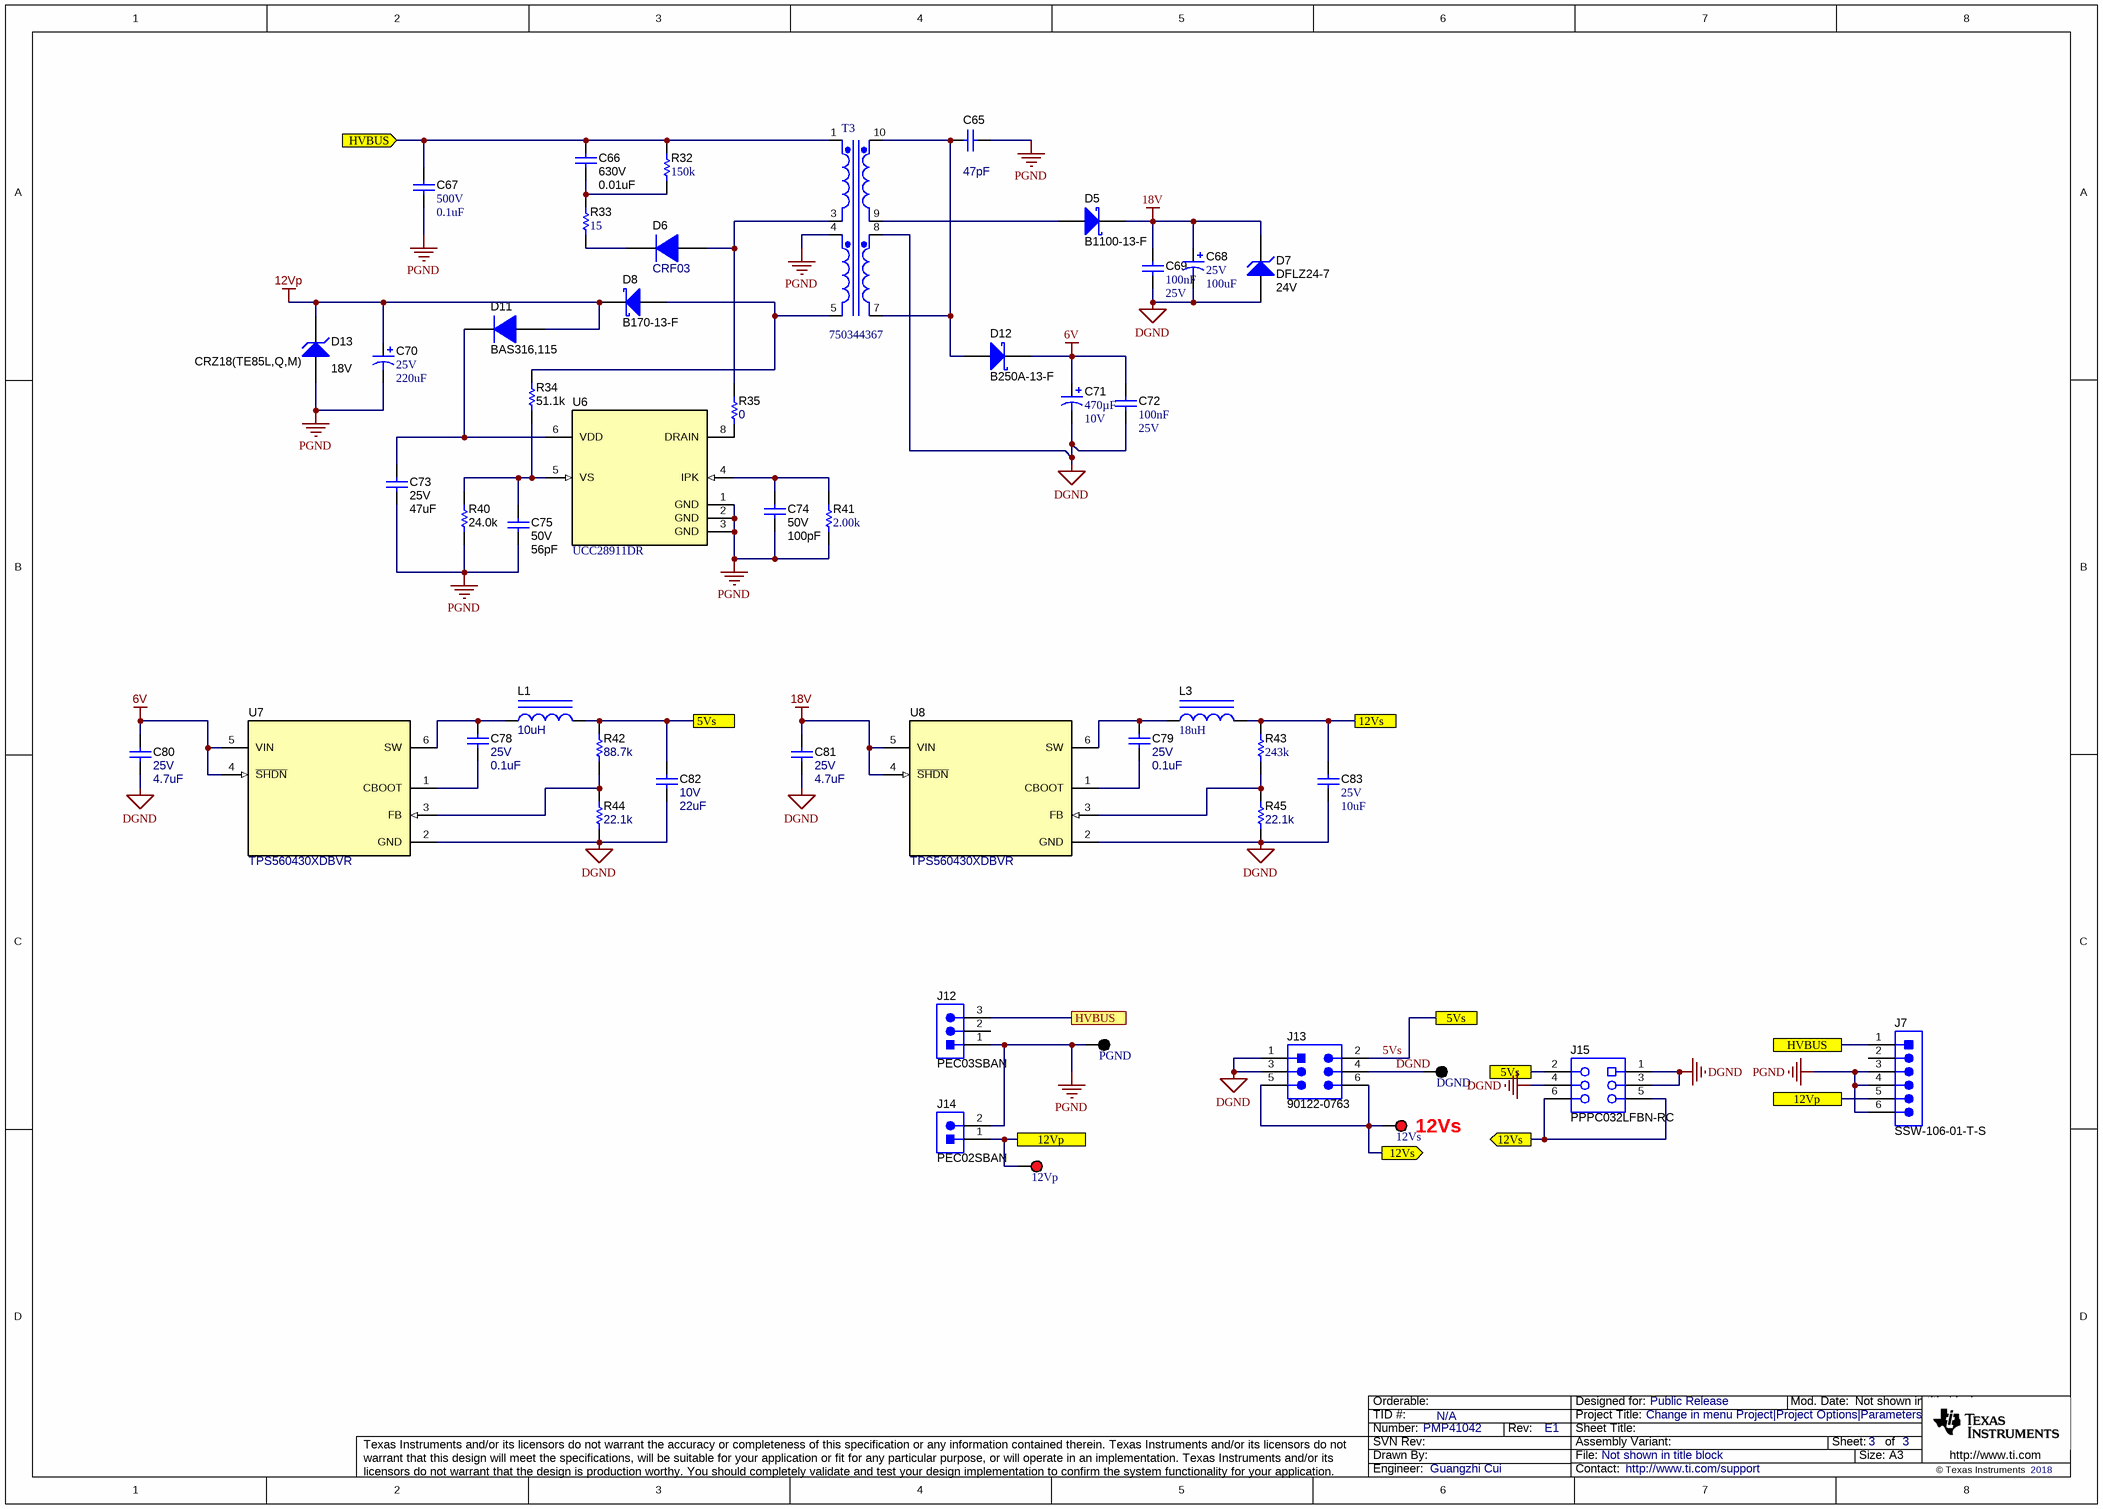
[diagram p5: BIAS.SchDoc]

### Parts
(Parts that share a designator on the sheet are numbered #1, #2 ... from top to bottom, then left to right.)
12Vp  5000  [Keystone5000]  (value not drawn)
12Vs  5000  [Keystone5000]  (value not drawn)
C65  ValueDisplayed: 47pF  [KY_700x500x1000]  (hidden comment: DE11XKX470JN4AC05F)
C66  VDC_V: 630V  ValueDisplayed: 0.01uF  [1206]  (hidden comment: GRM31BR72J103KW01L)
C67  VDC_V: 500V  ValueDisplayed: 0.1uF  [1210_250]  (hidden comment: C1210V104KCRACTU)
C68  VDC_V: 25V  ValueDisplayed: 100uF  [SVPF_E7]  (hidden comment: 25SVPF100M)
C69  Cap_F: 100nF  VDC_V: 25V  [0603]  (hidden comment: GCJ188R71E104KA12D)
C70  VDC_V: 25V  ValueDisplayed: 220uF  [Panasonic_D8]  (hidden comment: EEEFTE221XAP)
C71  ValueDisplayed: 470µF  VDC_V: 10V  [Panasonic_D8]  (hidden comment: EEE-FTA471XAP)
C72  Cap_F: 100nF  VDC_V: 25V  [0603]  (hidden comment: GCJ188R71E104KA12D)
C73  VDC_V: 25V  ValueDisplayed: 47uF  [1206]  (hidden comment: C3216JB1E476M160AC)
C74  VDC_V: 50V  ValueDisplayed: 100pF  [0603]  (hidden comment: C0603C101J5GAC)  (no BOM)
C75  VDC_V: 50V  ValueDisplayed: 56pF  [0603]  (hidden comment: GRM1885C1H560JA01D)  (no BOM)
C78  VDC_V: 25V  ValueDisplayed: 0.1uF  [0603]  (hidden comment: C1608X7R1E104K080AA)
C79  VDC_V: 25V  ValueDisplayed: 0.1uF  [0603]  (hidden comment: C1608X7R1E104K080AA)
C80  VDC_V: 25V  ValueDisplayed: 4.7uF  [0603]  (hidden comment: GRM188R61E475KE11D)
C81  VDC_V: 25V  ValueDisplayed: 4.7uF  [0603]  (hidden comment: GRM188R61E475KE11D)
C82  VDC_V: 10V  ValueDisplayed: 22uF  [0603]  (hidden comment: C1608X5R1A226M080AC)
C83  VDC_V: 25V  ValueDisplayed: 10uF  [0603]  (hidden comment: GRT188R61E106ME13D)
D5  B1100-13-F  [SMA]
D6  CRF03  [SOD-123H]
D7  DFLZ24-7  value 24V  [PowerDI123]
D8  B170-13-F  [SMA]
D11  BAS316,115  [SOD-323]
D12  B250A-13-F  [SMA]
D13  CRZ18(TE85L,Q,M)  value 18V  [SOD-123]
DGND  5001  [Keystone5001]  (value not drawn)
J7  SSW-106-01-T-S  [Samtec_SSW-106-01-x-S]
J12  PEC03SBAN  [Sullins_PEC03SBAN]
J13  90122-0763  [Molex_90122-0763]
J14  PEC02SBAN  [Sullins_xxC02SBAN]
J15  PPPC032LFBN-RC  [Sullins_xxxC032LFBN-RC]
L1  ValueDisplayed: 10uH  [VLS252010HBX]  (hidden comment: 74438323100)
L3  ValueDisplayed: 18uH  [WE-PD2A_4532]  (hidden comment: 784773118)
PGND#3  5001  [Keystone5001]  (value not drawn)
R32  ValueDisplayed: 150k  [1206]  (hidden comment: RCV1206150KFKEA)
R33  ValueDisplayed: 15  [0603]  (hidden comment: CRCW060315R0JNEA)
R34  ValueDisplayed: 51.1k  [0603]  (hidden comment: RC0603FR-0751K1L)
R35  ValueDisplayed: 0  [0603]  (hidden comment: RC0603JR-070RL)
R40  ValueDisplayed: 24.0k  [0603]  (hidden comment: RC0603FR-0724KL)
R41  ValueDisplayed: 2.00k  [0603]  (hidden comment: RT0603DRE072KL)
R42  ValueDisplayed: 88.7k  [0603]  (hidden comment: CRCW060388K7FKEA)
R43  ValueDisplayed: 243k  [0603]  (hidden comment: RT0603BRD07243KL)
R44  ValueDisplayed: 22.1k  [0603]  (hidden comment: CRCW060322K1FKEA)
R45  ValueDisplayed: 22.1k  [0603]  (hidden comment: CRCW060322K1FKEA)
T3  750344367  [Wurth_750315894]
U6  UCC28911DR  [D0007A_N]
U7  TPS560430XDBVR  [DBV0006A_N]
U8  TPS560430XDBVR  [DBV0006A_N]

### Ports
5Vs, 12Vp, 12Vs, 12Vs (out), HVBUS, HVBUS (in)

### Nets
6V: C71.1(+) C72.1 C80.1 D12.1(K) U7.4(~{SHDN}) U7.5(VIN)
12Vp: 12Vp.1 C70.1(+) D8.1(K) D11.2(A) D13.1(K) J7.5 J14.1 ; port 12Vp
18V: C68.1(+) C69.1 C81.1 D5.1(K) D7.1(K) U8.4(~{SHDN}) U8.5(VIN)
DGND: C68.2(-) C69.2 C71.2(-) C72.2 C80.2 C81.2 C82.2 C83.2 D7.2(A) DGND.1 J13.1 J13.3 J13.4 J15.1 J15.3 J15.4 R44.1 R45.1 T3.8(Sec2+) U7.2(GND) U8.2(GND)
PGND: C65.2 C67.2 C70.2(-) C73.2 C74.2 C75.2 D13.2(A) J7.3 J7.4 J7.6 J12.1 J14.2 PGND#3.1 R40.1 R41.1 T3.4(Pri2+) U6.1(GND) U6.2(GND) U6.3(GND)
5Vs: C82.1 J13.2 J15.2 L1.2 R42.2 ; port 5Vs
12Vs: 12Vs.1 C83.1 J13.5 J13.6 J15.5 J15.6 L3.2 R43.2 ; port 12Vs
HVBUS: C66.1 C67.1 J7.1 J12.3 R32.2 T3.1(Pri1+) ; port HVBUS
NetC65_1: C65.1 D12.2(A) T3.7(Sec2-) T3.10(Sec1+)
NetC66_2: C66.2 R32.1 R33.2
NetC73_1: C73.1 D11.1(K) U6.6(VDD)
NetC74_1: C74.1 R41.2 U6.4(IPK)
NetC75_1: C75.1 R34.1 R40.2 U6.5(VS)
NetC78_1: C78.1 L1.1 U7.6(SW)
NetC78_2: C78.2 U7.1(CBOOT)
NetC79_1: C79.1 L3.1 U8.6(SW)
NetC79_2: C79.2 U8.1(CBOOT)
NetD5_2: D5.2(A) T3.9(Sec1-)
NetD6_1: D6.1(K) R33.1
NetD6_2: D6.2(A) R35.2 T3.3(Pri1-)
NetD8_2: D8.2(A) R34.2 T3.5(Pri2-)
NetR35_1: R35.1 U6.8(DRAIN)
NetR42_1: R42.1 R44.2 U7.3(FB)
NetR43_1: R43.1 R45.2 U8.3(FB)

Not connected (* = marked no-connect by the designer): J7 2; J12 2

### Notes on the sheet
- 12Vs

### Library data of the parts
12Vp 12Vs = CMP-0055137-1: Test Point, Miniature, Red, TH; Manufacturer: Keystone; ContactFinish: Silver; Green_Lifecycle: Active; Green_REACh: Passed; CNHeader: FALSE; CT: TRUE
C65 = CMP-0009608-4: CAP, CERM, 47 pF, X1 250 VAC/Y1 300 VAC, +/- 10%, B, TH; Manufacturer: MuRata; TaMin_C: -25°C; Polarized: N; SizeAreaWB_mm2: 66.5; Value1: Unknown; U/M: EA; Value: 47pF; TaMax_C: 85°C; SizeZ_mm: 13; SizeX_mm: 9; SizeY_mm: 5; Cap_Case: 7x5x10mm; SizeArea_mm2: 37.5; AEC Category: Q200; AC_Safety: X1Y2; VAC_X: 250V; VAC_Y: 300V
C66 = CMP-0008910-2: CAP, CERM, 0.01 uF, 630 V, +/- 10%, X7R, 1206; Manufacturer: MuRata; TaMin_C: -55°C; Polarized: N; SizeAreaWB_mm2: 10.92; Value1: Unknown; U/M: EA; Value: 0.01uF; TaMax_C: 125°C; SizeZ_mm: 1.35; SizeX_mm: 3.2; SizeY_mm: 1.6; SizeArea_mm2: 5.12; Cap_F: 10nF; AEC Category: Q200
C67 = CMP-0009092-1: CAP, CERM, 0.1 uF, 500 V, +/- 10%, X7R,; Manufacturer: Kemet; TaMin_C: -55°C; Polarized: N; SizeAreaWB_mm2: 14.7; Value1: Unknown; U/M: EA; Value: 0.1uF; TaMax_C: 125°C; SizeZ_mm: 2.5; SizeX_mm: 3.2; Cap_Case: 1210; SizeArea_mm2: 8; Cap_F: 100nF; AEC Category: Q200
C68 = CMP-0012117-3: CAP, Aluminum Polymer, 100 uF, 25 V, +/- 20%, 0.024 ohm, 8.0x7.0mm SMD; Manufacturer: Panasonic; TaMin_C: -55°C; ESR_ohm: 24m; Polarized: Y; Value: 100uF; TaMax_C: 105°C; CompType: Capacitor; Cap_F: 100µF; IRMS_A: 3.2A; AEC Category: Q200
C69 C72 = CMP-0007404-4: CAP, CERM, 0.1 uF, 25 V, +/- 10%, X7R, 0603; Manufacturer: MuRata; TaMin_C: -55°C; Polarized: N; SizeAreaWB_mm2: 4.68; Value1: Unknown; U/M: EA; Value: 0.1uF; TaMax_C: 125°C; SizeZ_mm: 1; SizeX_mm: 1.6; SizeY_mm: 0.8; SizeArea_mm2: 1.28; AEC Category: Q200
C70 = CMP-0010738-1: CAP, AL, 220 uF, 25 V, +/- 20%, 0.16 ohm, AEC-Q200 Grade 2, SMD; Manufacturer: Panasonic; TaMin_C: -55°C; ESR_ohm: 0.16; Polarized: Y; SizeAreaWB_mm2: 73.96; U/M: EA; Value: 220uF; TaMax_C: 105°C; SizeZ_mm: 8; SizeX_mm: 6.6; Cap_Case: 6.3x7.7mm; SizeArea_mm2: 43.56; CompType: Capacitor; Cap_F: 220µF; IRMS_A: 600mA; AEC Grade: 2; AEC Category: Q200
C71 = CMP-0084632-1: CAP, AL, 470 µF, 10 V, +/- 20%, 0.16 ohm, AEC-Q200 Grade 2, SMD; Manufacturer: Panasonic; U/M: EA; SizeArea_mm2: 43.56; ESR_ohm: 0.16; AEC Category: Q200; SizeY_mm: 6.6; Value: 470uF; TaMin_C: -55°C; TaMax_C: 105°C; SizeAreaWB_mm2: 73.96; CompType: Capacitor; AEC Qualified: Y; Cap_Case: 6.6x6.6x8mm; AEC Grade: 2; SizeZ_mm: 8
C73 = CMP-0008646-2: CAP, CERM, 47 uF, 25 V, +/- 20%, JB, 1206; Manufacturer: TDK; TaMin_C: -55°C; Polarized: N; SizeAreaWB_mm2: 10.92; Value1: Unknown; U/M: EA; Value: 47uF; TaMax_C: 85°C; SizeZ_mm: 1.35; SizeX_mm: 3.2; SizeY_mm: 1.6; SizeArea_mm2: 5.12; Cap_F: 47µF; AEC Category: Q200
C74 = CMP-0006840-4: CAP, CERM, 100 pF, 50 V, +/- 5%, C0G/NP0, 0603; Manufacturer: Kemet; TaMin_C: -55°C; Polarized: N; SizeAreaWB_mm2: 4.68; Value1: Unknown; U/M: EA; Value: 100pF; TaMax_C: 125°C; SizeZ_mm: 1; SizeX_mm: 1.6; SizeY_mm: 0.8; SizeArea_mm2: 1.28; AEC Category: Q200
C75 = CMP-0007224-4: CAP, CERM, 56 pF, 50 V, +/- 5%, C0G/NP0, 0603; Manufacturer: MuRata; TaMin_C: -55°C; Polarized: N; SizeAreaWB_mm2: 4.68; Value1: Unknown; U/M: EA; Value: 56pF; TaMax_C: 125°C; SizeZ_mm: 1; SizeX_mm: 1.6; SizeY_mm: 0.8; SizeArea_mm2: 1.28; AEC Category: Q200
C78 C79 = CMP-0007039-5: CAP, CERM, 0.1 uF, 25 V, +/- 10%, X7R, 0603; Manufacturer: TDK; TaMin_C: -55°C; Polarized: N; SizeAreaWB_mm2: 4.68; Value1: Unknown; U/M: EA; Value: 0.1uF; TaMax_C: 125°C; SizeZ_mm: 1; SizeX_mm: 1.6; SizeY_mm: 0.8; SizeArea_mm2: 1.28; Cap_F: 100nF; AEC Category: Q200
C80 C81 = CMP-0007347-1: CAP, CERM, 4.7 uF, 25 V, +/- 10%, X5R, 0603; Manufacturer: MuRata; TaMin_C: -55°C; Polarized: N; SizeAreaWB_mm2: 4.68; Value1: Unknown; U/M: EA; Value: 4.7uF; TaMax_C: 85°C; SizeZ_mm: 1; SizeX_mm: 1.6; SizeY_mm: 0.8; SizeArea_mm2: 1.28; Cap_F: 4.7µF; AEC Category: Q200
C82 = CMP-0007005-1: CAP, CERM, 22 uF, 10 V, +/- 20%, X5R, 0603; Manufacturer: TDK; TaMin_C: -55°C; ESR_ohm: 3.71m; Polarized: N; SizeAreaWB_mm2: 4.68; Value1: 0.00371 ohm; U/M: EA; Value: 22uF; TaMax_C: 85°C; SizeZ_mm: 1; SizeX_mm: 1.6; SizeY_mm: 0.8; SizeArea_mm2: 1.28; Cap_F: 22µF; IRMS_A: 2.69936A; AEC Category: Q200
C83 = CMP-0007501-4: CAP, CERM, 10 uF, 25 V, +/- 20%, X5R, 0603; Manufacturer: MuRata; TaMin_C: -55°C; Polarized: N; SizeAreaWB_mm2: 4.68; Value1: Unknown; U/M: EA; Value: 10uF; TaMax_C: 85°C; SizeZ_mm: 1; SizeX_mm: 1.6; SizeY_mm: 0.8; SizeArea_mm2: 1.28; Cap_F: 10µF; AEC Category: Q200
D5 = CMP-0028371-1: Diode, Schottky, 100 V, 1 A, SMA; Manufacturer: Diodes Inc.; Io_A: 1A; Green_Lifecycle: Active; SizeAreaWB_mm2: 37.3428; Vr_V: 100V; Green_REACh: Passed; TJmax_C: 150°C; U/M: EA; Value: 100V; SizeZ_mm: 2.87; SizeX_mm: 5.59; SizeY_mm: 2.92; Vf_V: 790mV; Value2: 0.79V; SizeArea_mm2: 16.3228; AEC Category: Q101; RJC_CperW: 25
D6 = CMP-0077074-2: Diode, Superfast Rectifier, 600 V, 1 A, 3.5x1.6mm; Manufacturer: Toshiba; Value: 600V; SizeY_mm: 1.6; Value2: 1.7V; Value1: 1A; Io_A: 0.7A; Green_Lifecycle: Not Set; AEC Category: Q101; SizeX_mm: 3.5; SizeAreaWB_mm2: 11.7; SizeZ_mm: 1.0; Green_REACh: Incomplete; SizeArea_mm2: 5.6; TJmax_C: 150°C; AEC Qualified: N
D7 = CMP-0005415-4: Diode, Zener, 24 V, 1 W, PowerDI123; Manufacturer: Diodes Inc.; Power_W: 1W; RJA_CperW: 110; SizeAreaWB_mm2: 13.066; SizeZ_mm: 0.98; SizeX_mm: 3.7; AEC Category: Q101; SizeY_mm: 1.78; SizeArea_mm2: 6.586
D8 = CMP-0028391-2: Diode, Schottky, 70 V, 1 A, SMA; Manufacturer: Diodes Inc.; SizeAreaWB_mm2: 37.3428; RJC_CperW: 25; Io_A: 1A; AEC Category: Q101; Green_Lifecycle: Active; SizeZ_mm: 2.87; Value: 70V; Vf_V: 7.9dV; SizeY_mm: 2.92; Green_REACh: Passed; Value2: 0.79V; SizeX_mm: 5.59; TJmax_C: 150°C; SizeArea_mm2: 16.3228
D11 = CMP-0029006-1: Diode, Ultrafast, 100 V, 0.25 A, SOD-323; Manufacturer: Nexperia; Io_A: 250mA; Green_Lifecycle: Not Set; SizeAreaWB_mm2: 8.695; Vr_V: 100V; Green_REACh: Incomplete; Value1: 0.25A; TJmax_C: 150°C; U/M: EA; Value: 100V; SizeZ_mm: 1; SizeX_mm: 2.7; SizeY_mm: 1.35; Vf_V: 1.4V; SizeArea_mm2: 3.645; AEC Category: Q101
D12 = CMP-0028405-2: Diode, Schottky, 50 V, 2 A, SMA; Manufacturer: Diodes Inc.; SizeArea_mm2: 16.3228; RJC_CperW: 20; Vr_V: 50V; SizeX_mm: 5.59; Green_REACh: Incomplete; SizeY_mm: 2.92; Green_Lifecycle: Not Set; Value2: 0.7V; Io_A: 2A; Value: 50V; SizeZ_mm: 2.87; SizeAreaWB_mm2: 37.3428; AEC Category: Q101; TJmax_C: 150°C; Vf_V: 7dV
D13 = CMP-0005747-4: Diode, Zener, 18 V, 700 mW, SOD-123; Manufacturer: Toshiba; SizeAreaWB_mm2: 13.095; SizeArea_mm2: 6.545; SizeX_mm: 3.85; Value1: 0.7W; SizeY_mm: 1.7; Power_W: 700mW; SizeZ_mm: 1.35; RJA_CperW: 340; AEC Category: Q101
DGND PGND#3 = CMP-0055138-1: Test Point, Miniature, Black, TH; Manufacturer: Keystone; ContactFinish: Silver; Green_Lifecycle: Active; Green_REACh: Passed; CNHeader: FALSE; CT: TRUE
J7 = CMP-0075621-1: Receptacle, 6x1, 2.54mm, Tin, TH; Manufacturer: Samtec; Pitch_mm: 2.54; Gender: Female; Cert_CSA: Y; Current_A: 5.7A; CT: False; Row_Count: 1
J12 = CMP-0054704-1: Header, 100mil, 3x1, Tin, R/A, TH; Manufacturer: Sullins Connector Solutions; CNHeader: FALSE; Current_A: 3A; Green_Lifecycle: Not Set; Shrouded: N; Gender: Male; Green_REACh: Incomplete; Voltage_V: 1.8kV; Row_Count: 1; Pitch_mm: 2.54; Cert_UL: Y
J13 = CMP-0077741-2: Header, 2.54mm, 3x2, Gold, R/A, TH; Manufacturer: Molex; Pitch_mm: 2.54; Gender: Male; Cert_UL: Y; Current_A: 3A; Voltage_V: 350V; Shrouded: N; Row_Count: 2
J14 = CMP-0054712-1: Header, 2.54 mm, 2x1, Tin, R/A, TH; Manufacturer: Sullins Connector Solutions; CNHeader: FALSE; Current_A: 3A; Shrouded: N; Gender: Male; Voltage_V: 1.8kV; Row_Count: 1; Pitch_mm: 2.54; Cert_UL: Y
J15 = CMP-0082513-1: Receptacle, 2.54mm, 3x2, Gold, TH; Manufacturer: Sullins Connector Solutions; Pitch_mm: 2.54; Gender: Female; Cert_UL: Y; Voltage_V: 250V; Current_A: 3A; Row_Count: 2; CompType: Socket Strip
L1 = CMP-0063086-1: Inductor, Wirewound, Ferrite, 10 uH, 0.68 A, 0.46 ohm, SMD; Manufacturer: Würth Elektronik; Isat: 1.35A @ 20% inductance drop; Irms: 0.60A @ 40C rise; Green_Lifecycle: Active; SizeAreaWB_mm2: 10.5; DCR_ohm: 0.46; Green_REACh: Passed; Value1: 0.843 ohm; Value: 10uH; Imax_A: 600mA; SizeZ_mm: 1; SizeX_mm: 2.5; SizeY_mm: 2; Value2: 0.6A; SizeArea_mm2: 5; Ind_H: 10µH; AEC Qualified: N; AEC Category: Q200
L3 = CMP-0064687-1: Inductor, Wirewound, Ferrite, 18 uH, 1.1 A, 0.225 ohm, AEC-Q200 Grade 1, SMD; Manufacturer: Wurth Elektronik; Isat: 1.29A @ 20% inductance drop; Irms: 1.1A @ 40C rise; Green_Lifecycle: Active; SizeAreaWB_mm2: 27.5; DCR_ohm: 0.225; Green_REACh: Passed; Value: 18uH; Imax_A: 1.1A; SizeZ_mm: 3.5; SizeX_mm: 4; SizeY_mm: 4.5; SizeArea_mm2: 18; Ind_H: 18µH; AEC Qualified: Y; AEC Grade: 1; AEC Category: Q200
R32 = CMP-0018591-3: RES, 150 k, 5%, 0.25 W, 1206; Manufacturer: Vishay-Dale; Power_W: 250mW; TempCo: 200 ppm/C; Value: 150k; EIA_Code: E24; SizeX_mm: 3.2; SizeY_mm: 1.6; SizeZ_mm: 1.35; Value2: 0.25W; SizeArea_mm2: 5.12; AEC Qualified: Y; VDC_V: 200V; AEC Category: Q200; AEC Grade: 0
R33 = CMP-0025720-4: RES, 15, 5%, 0.1 W, AEC-Q200 Grade 0, 0603; Manufacturer: Vishay-Dale; Power_W: 100mW; TempCo: 200 ppm/C; Value_Code: 15R0; Value: 15; EIA_Code: E24; SizeX_mm: 1.6; SizeY_mm: 0.8; SizeZ_mm: 1; Value2: 0.1W; SizeArea_mm2: 1.28; AEC Qualified: Y; VDC_V: 75V; AEC Category: Q200; AEC Grade: 0
R34 = CMP-0023166-5: RES, 51.1 k, 1%, 0.1 W, 0603; Manufacturer: Yageo; Power_W: 100mW; TempCo: 100 ppm/C; Value_Code: 51k1; Value: 51.1k; EIA_Code: E96; SizeX_mm: 1.6; SizeY_mm: 0.8; SizeZ_mm: 1; Value2: 0.1W; SizeArea_mm2: 1.28; AEC Qualified: N; VDC_V: 75V; AEC Category: Q200; SizeAreaWB_mm2: 4.68
R35 = CMP-0025885-5: RES, 0, 5%, 0.1 W, 0603; Manufacturer: Yageo; Power_W: 100mW; TempCo: 200 ppm/C; Value_Code: 0000; Value: 0; EIA_Code: E24; SizeX_mm: 1.6; SizeZ_mm: 1; Value2: 0.1W; SizeArea_mm2: 1.28; AEC Qualified: N; VDC_V: 75V; AEC Category: Q200; SizeY_mm: 0.8; SizeAreaWB_mm2: 4.68
R40 = CMP-0022945-5: RES, 24.0 k, 1%, 0.1 W, 0603; Manufacturer: Yageo; Power_W: 100mW; TempCo: 100 ppm/C; Value_Code: 24k0; Value: 24.0k; Res_ohm: 24k; SizeX_mm: 1.6; SizeY_mm: 0.8; SizeZ_mm: 1; Value2: 0.1W; SizeArea_mm2: 1.28; AEC Qualified: N; VDC_V: 75V; AEC Category: Q200; SizeAreaWB_mm2: 4.68
R41 = CMP-0025080-1: RES, 2.00 k, 0.5%, 0.1 W, 0603; Manufacturer: Yageo America; Power_W: 100mW; TempCo: 50 ppm/C; Value_Code: 2k00; U/M: EA; Value: 2.00k; EIA_Code: E192; Res_ohm: 2k; SizeX_mm: 1.6; SizeY_mm: 0.8; SizeZ_mm: 1; Value2: 0.1W; SizeArea_mm2: 1.28; VDC_V: 75V; AEC Category: Q200
R42 = CMP-0022632-1: RES, 88.7 k, 1%, 0.1 W, 0603; Manufacturer: Vishay-Dale; Power_W: 100mW; TempCo: 100 ppm/C; Value_Code: 88k7; U/M: EA; Value: 88.7k; EIA_Code: E96; SizeX_mm: 1.6; SizeY_mm: 0.8; SizeZ_mm: 1; Value2: 0.1W; SizeArea_mm2: 1.28; VDC_V: 75V; AEC Category: Q200
R43 = CMP-0023982-2: RES, 243 k, 0.1%, 0.1 W, 0603; Manufacturer: Yageo America; Power_W: 100mW; TempCo: 25 ppm/C; U/M: EA; Value: 243k; EIA_Code: E192; SizeX_mm: 1.6; SizeY_mm: 0.8; SizeZ_mm: 1; Value2: 0.1W; SizeArea_mm2: 1.28; VDC_V: 75V; AEC Category: Q200
R44 R45 = CMP-0022220-1: RES, 22.1 k, 1%, 0.1 W, 0603; Manufacturer: Vishay-Dale; Power_W: 100mW; TempCo: 100 ppm/C; Value_Code: 22k1; U/M: EA; Value: 22.1k; EIA_Code: E96; SizeX_mm: 1.6; SizeY_mm: 0.8; SizeZ_mm: 1; Value2: 0.1W; SizeArea_mm2: 1.28; VDC_V: 75V; AEC Category: Q200
T3 = Trans BB: flyback transformer for UCC28911 dual output; Manufacturer: Wurth Elektronik
U6 = CMP-0074093-2: 700V Flyback Switcher with Constant-Voltage Constant-Current and Primary-side Regulation, D0007A (SOIC-7); Alternate Manufacturer: Texas Instruments; SizeAreaWB_mm2: 55.2; U/M: EA; SizeZ_mm: 1.75; SizeX_mm: 6.0; SizeY_mm: 4.9; SizeArea_mm2: 29.4; CompType: IC; AEC Category: Q200; AEC Qualified: N
U7 U8 = CMP-0065097-1: 4V to 36 V 0.6 A Synchronous Step-Down Converter, DBV0006A (SOT-23-6); Alternate PartNumber: TPS560430XDBVT; Alternate Manufacturer: Texas Instruments; SizeAreaWB_mm2: 14.82; U/M: EA; SizeZ_mm: 1.45; SizeX_mm: 2.8; SizeY_mm: 2.9; SizeArea_mm2: 8.12; CompType: IC

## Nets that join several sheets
12Vp: PMP41042_sheet2 (7 pins), BIAS (7 pins)
DGND: PMP41042_sheet1 (84 pins), PMP41042_sheet2 (86 pins), BIAS (21 pins)
PGND: PMP41042_sheet1 (17 pins), PMP41042_sheet2 (23 pins), BIAS (19 pins)
1V65: PMP41042_sheet1 (C42.2 R25.1), PMP41042_sheet2 (C151.1 U12.1 U20.1)
3.3Vs: PMP41042_sheet1 (6 pins), PMP41042_sheet2 (15 pins)
5Vp: PMP41042_sheet1 (6 pins), PMP41042_sheet2 (8 pins)
5Vs: PMP41042_sheet1 (6 pins), PMP41042_sheet2 (18 pins), BIAS (5 pins)
12Vs: PMP41042_sheet2 (11 pins), BIAS (8 pins)
48Vo-: PMP41042_sheet1 (6 pins), PMP41042_sheet2 (R72.1)
COIL_PRI_N: PMP41042_sheet1 (L5.2), PMP41042_sheet2 (5 pins)
COIL_PRI_P: PMP41042_sheet1 (L5.1), PMP41042_sheet2 (R56.1)
COIL_SEC_N: PMP41042_sheet1 (L2.1), PMP41042_sheet2 (5 pins)
COIL_SEC_P: PMP41042_sheet1 (L2.2), PMP41042_sheet2 (R66.1)
GaN_SW1: PMP41042_sheet1 (T2.2), PMP41042_sheet2 (GaN_SW1#1.1 GaN_SW1#2.1)
GaN_SW2: PMP41042_sheet1 (8 pins), PMP41042_sheet2 (GaN_SW2#1.1 GaN_SW2#2.1)
HVBUS: PMP41042_sheet1 (9 pins), PMP41042_sheet2 (HVBUS1.1 HVBUS2.1 HVBUS#1.1 HVBUS#2.1), BIAS (6 pins)
ISNS_PRI: PMP41042_sheet1 (C25.1 R14.2 U2.1), PMP41042_sheet2 (R84.1)
ISNS_PRI_TANK1: PMP41042_sheet1 (C26.1 R6.1), PMP41042_sheet2 (R59.1)
SEC_SW1: PMP41042_sheet1 (33 pins), PMP41042_sheet2 (C105.2 C106.2 U14.4)
SEC_SW2: PMP41042_sheet1 (49 pins), PMP41042_sheet2 (C120.2 C121.2 U15.4)
SR_HA: PMP41042_sheet1 (R36.1), PMP41042_sheet2 (U14.3)
SR_HB: PMP41042_sheet1 (R37.2), PMP41042_sheet2 (U15.3)
SR_LA: PMP41042_sheet1 (R47.1), PMP41042_sheet2 (U14.8)
SR_LB: PMP41042_sheet1 (R48.2), PMP41042_sheet2 (U15.8)
VSNS_PRI: PMP41042_sheet1 (C29.2 R16.2 U3.1), PMP41042_sheet2 (R81.2)
VSNS_SEC: PMP41042_sheet1 (U1.1 U1.4), PMP41042_sheet2 (R83.2)

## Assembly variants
001: not fitted FID1 FID2 FID3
